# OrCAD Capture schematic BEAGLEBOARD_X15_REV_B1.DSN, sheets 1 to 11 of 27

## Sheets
1 P01_TITLE PAGE: title: BeagleBoard-X15; rev: B1; note: BeagleBoard-X15-_B.dsn
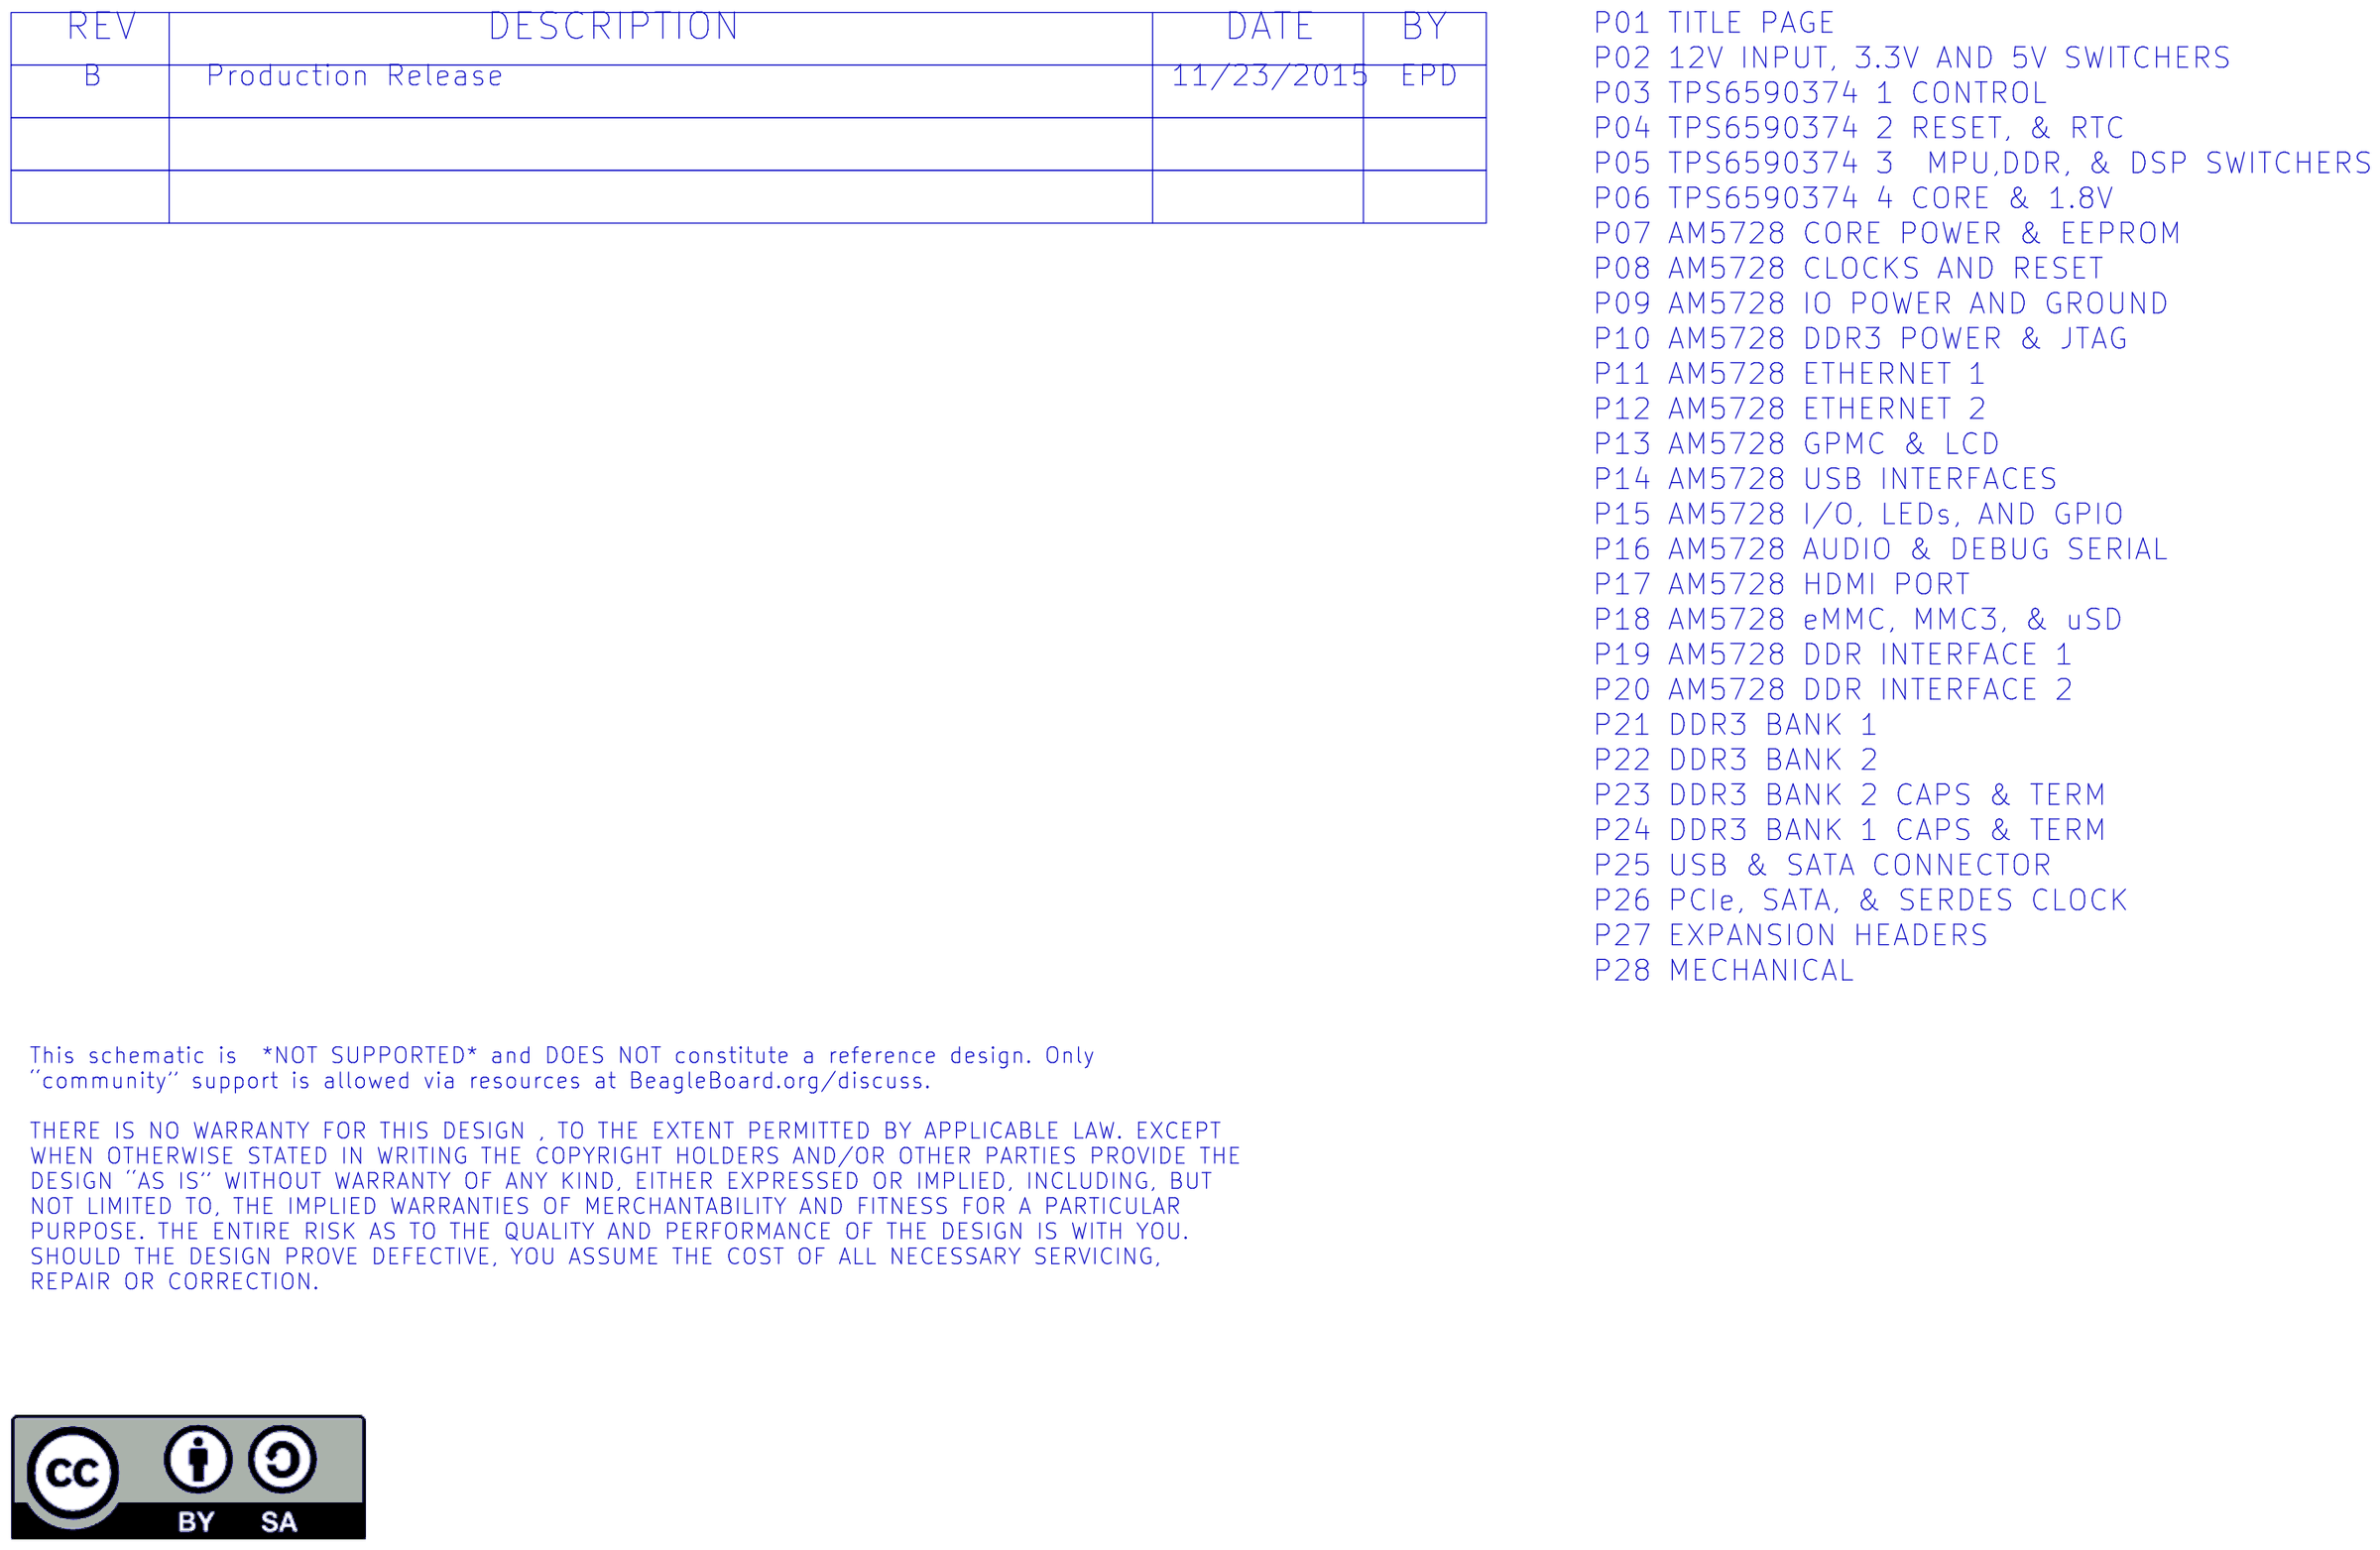
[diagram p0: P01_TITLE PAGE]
2 P02_12V IN, 3.3V & 5V SWITCHERS: size B; title: BeagleBoard-X15 12V in,3,3V & 5V SWITCHERS; note: BeagleBoard-X15_A2.dsn
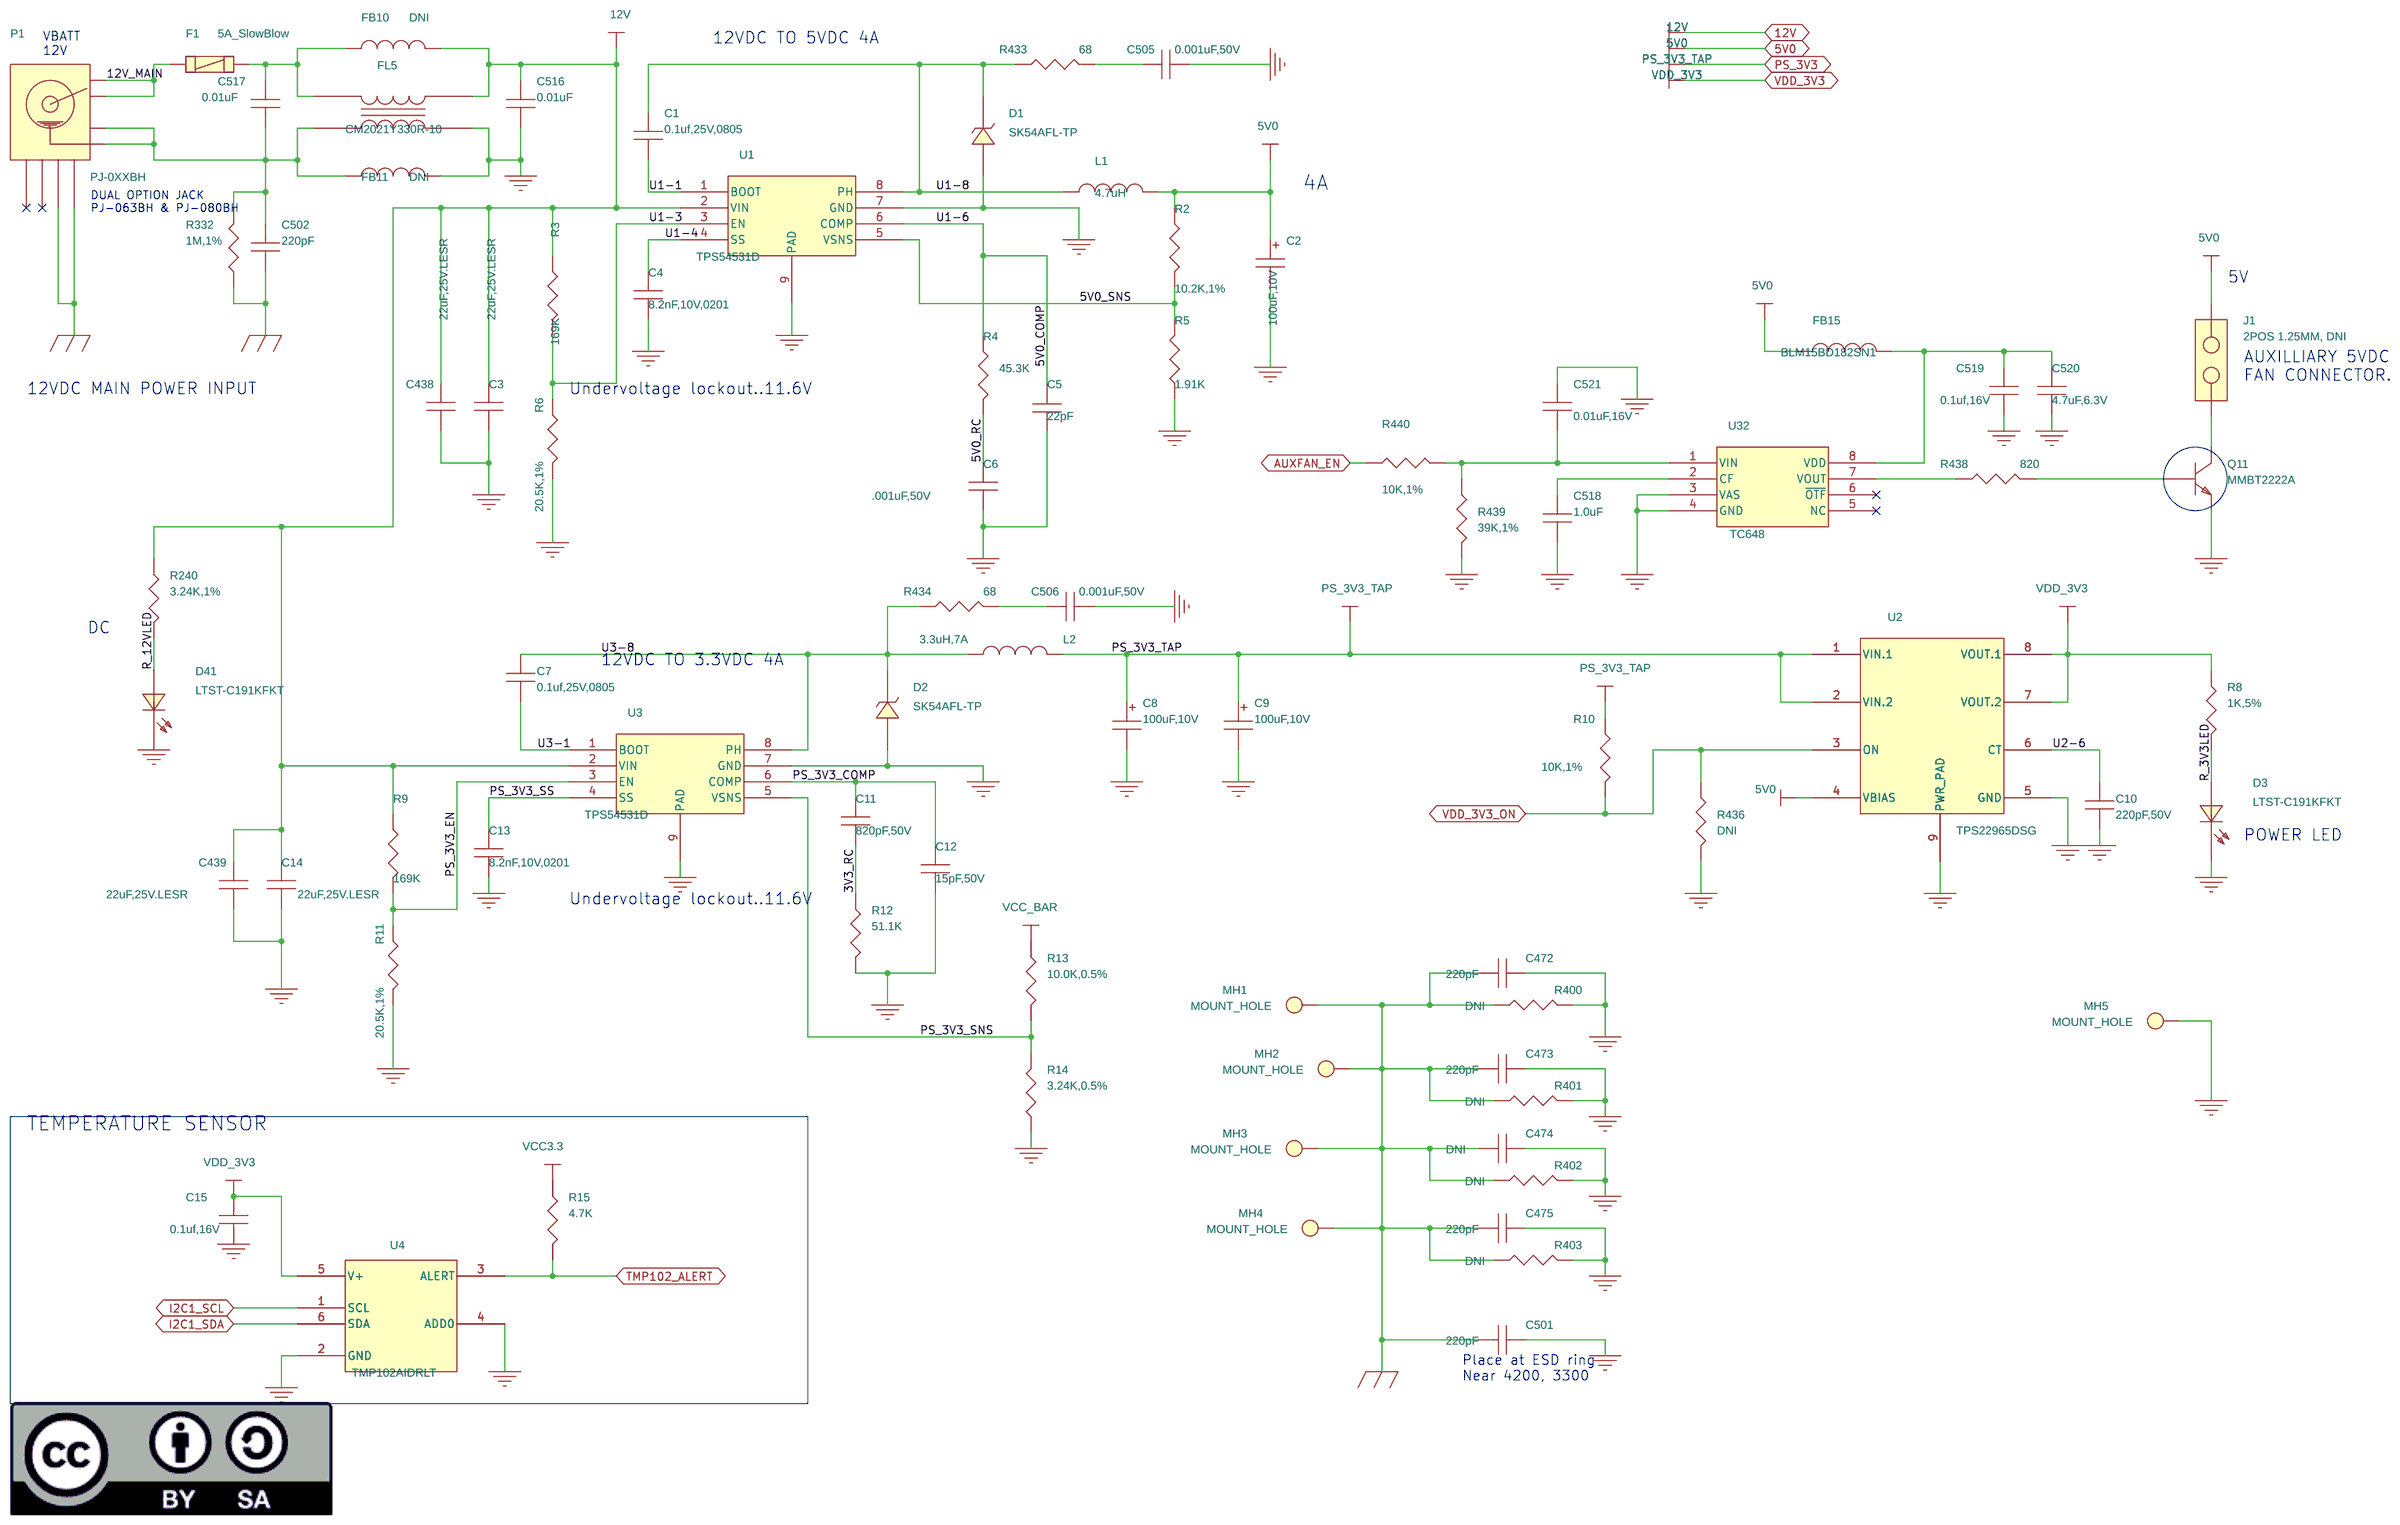
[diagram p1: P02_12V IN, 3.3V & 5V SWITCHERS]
3 P03_TPS6590376 CONTROL: size B; title: BeagleBoard-X15 TPS6590371 CONTROL; note: BeagleBoard-X15_B.dsn
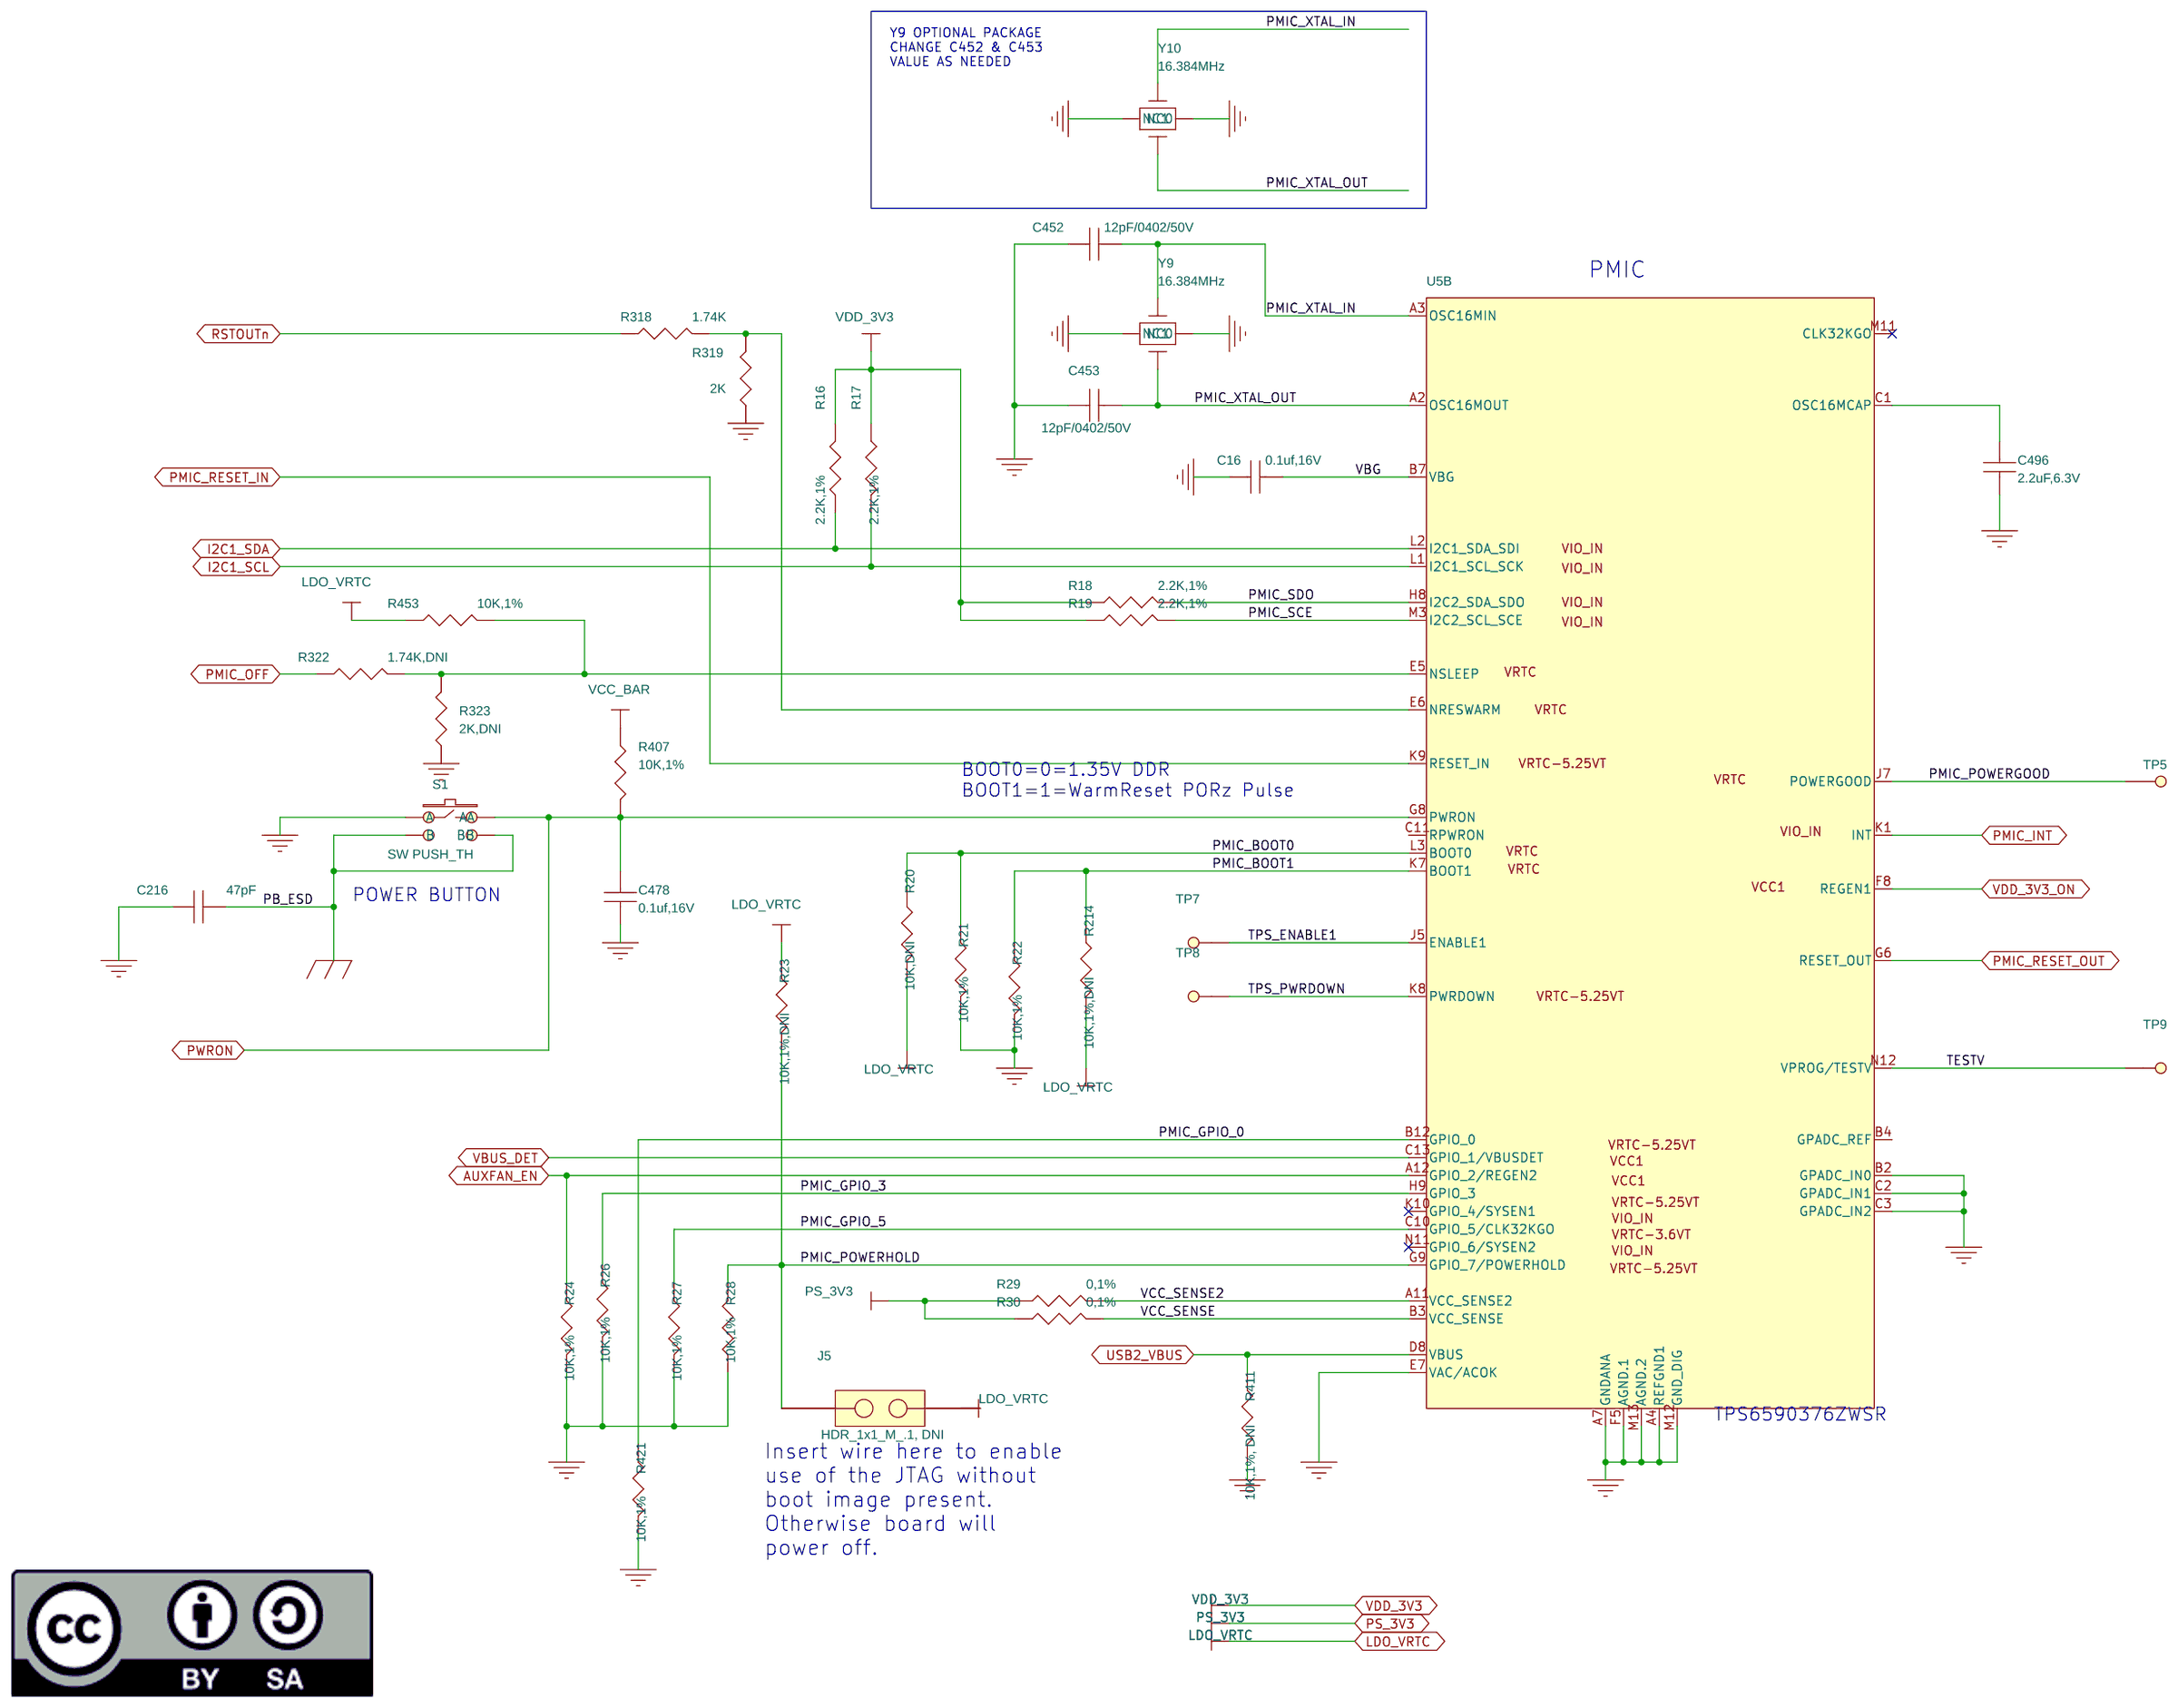
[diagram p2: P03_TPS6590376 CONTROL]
4 P04_TPS6590376 2, LDO & RTC: size B; title: BeagleBoard-X15 TPS6590371 CONTROL; note: BeagleBoard-X15_B.dsn
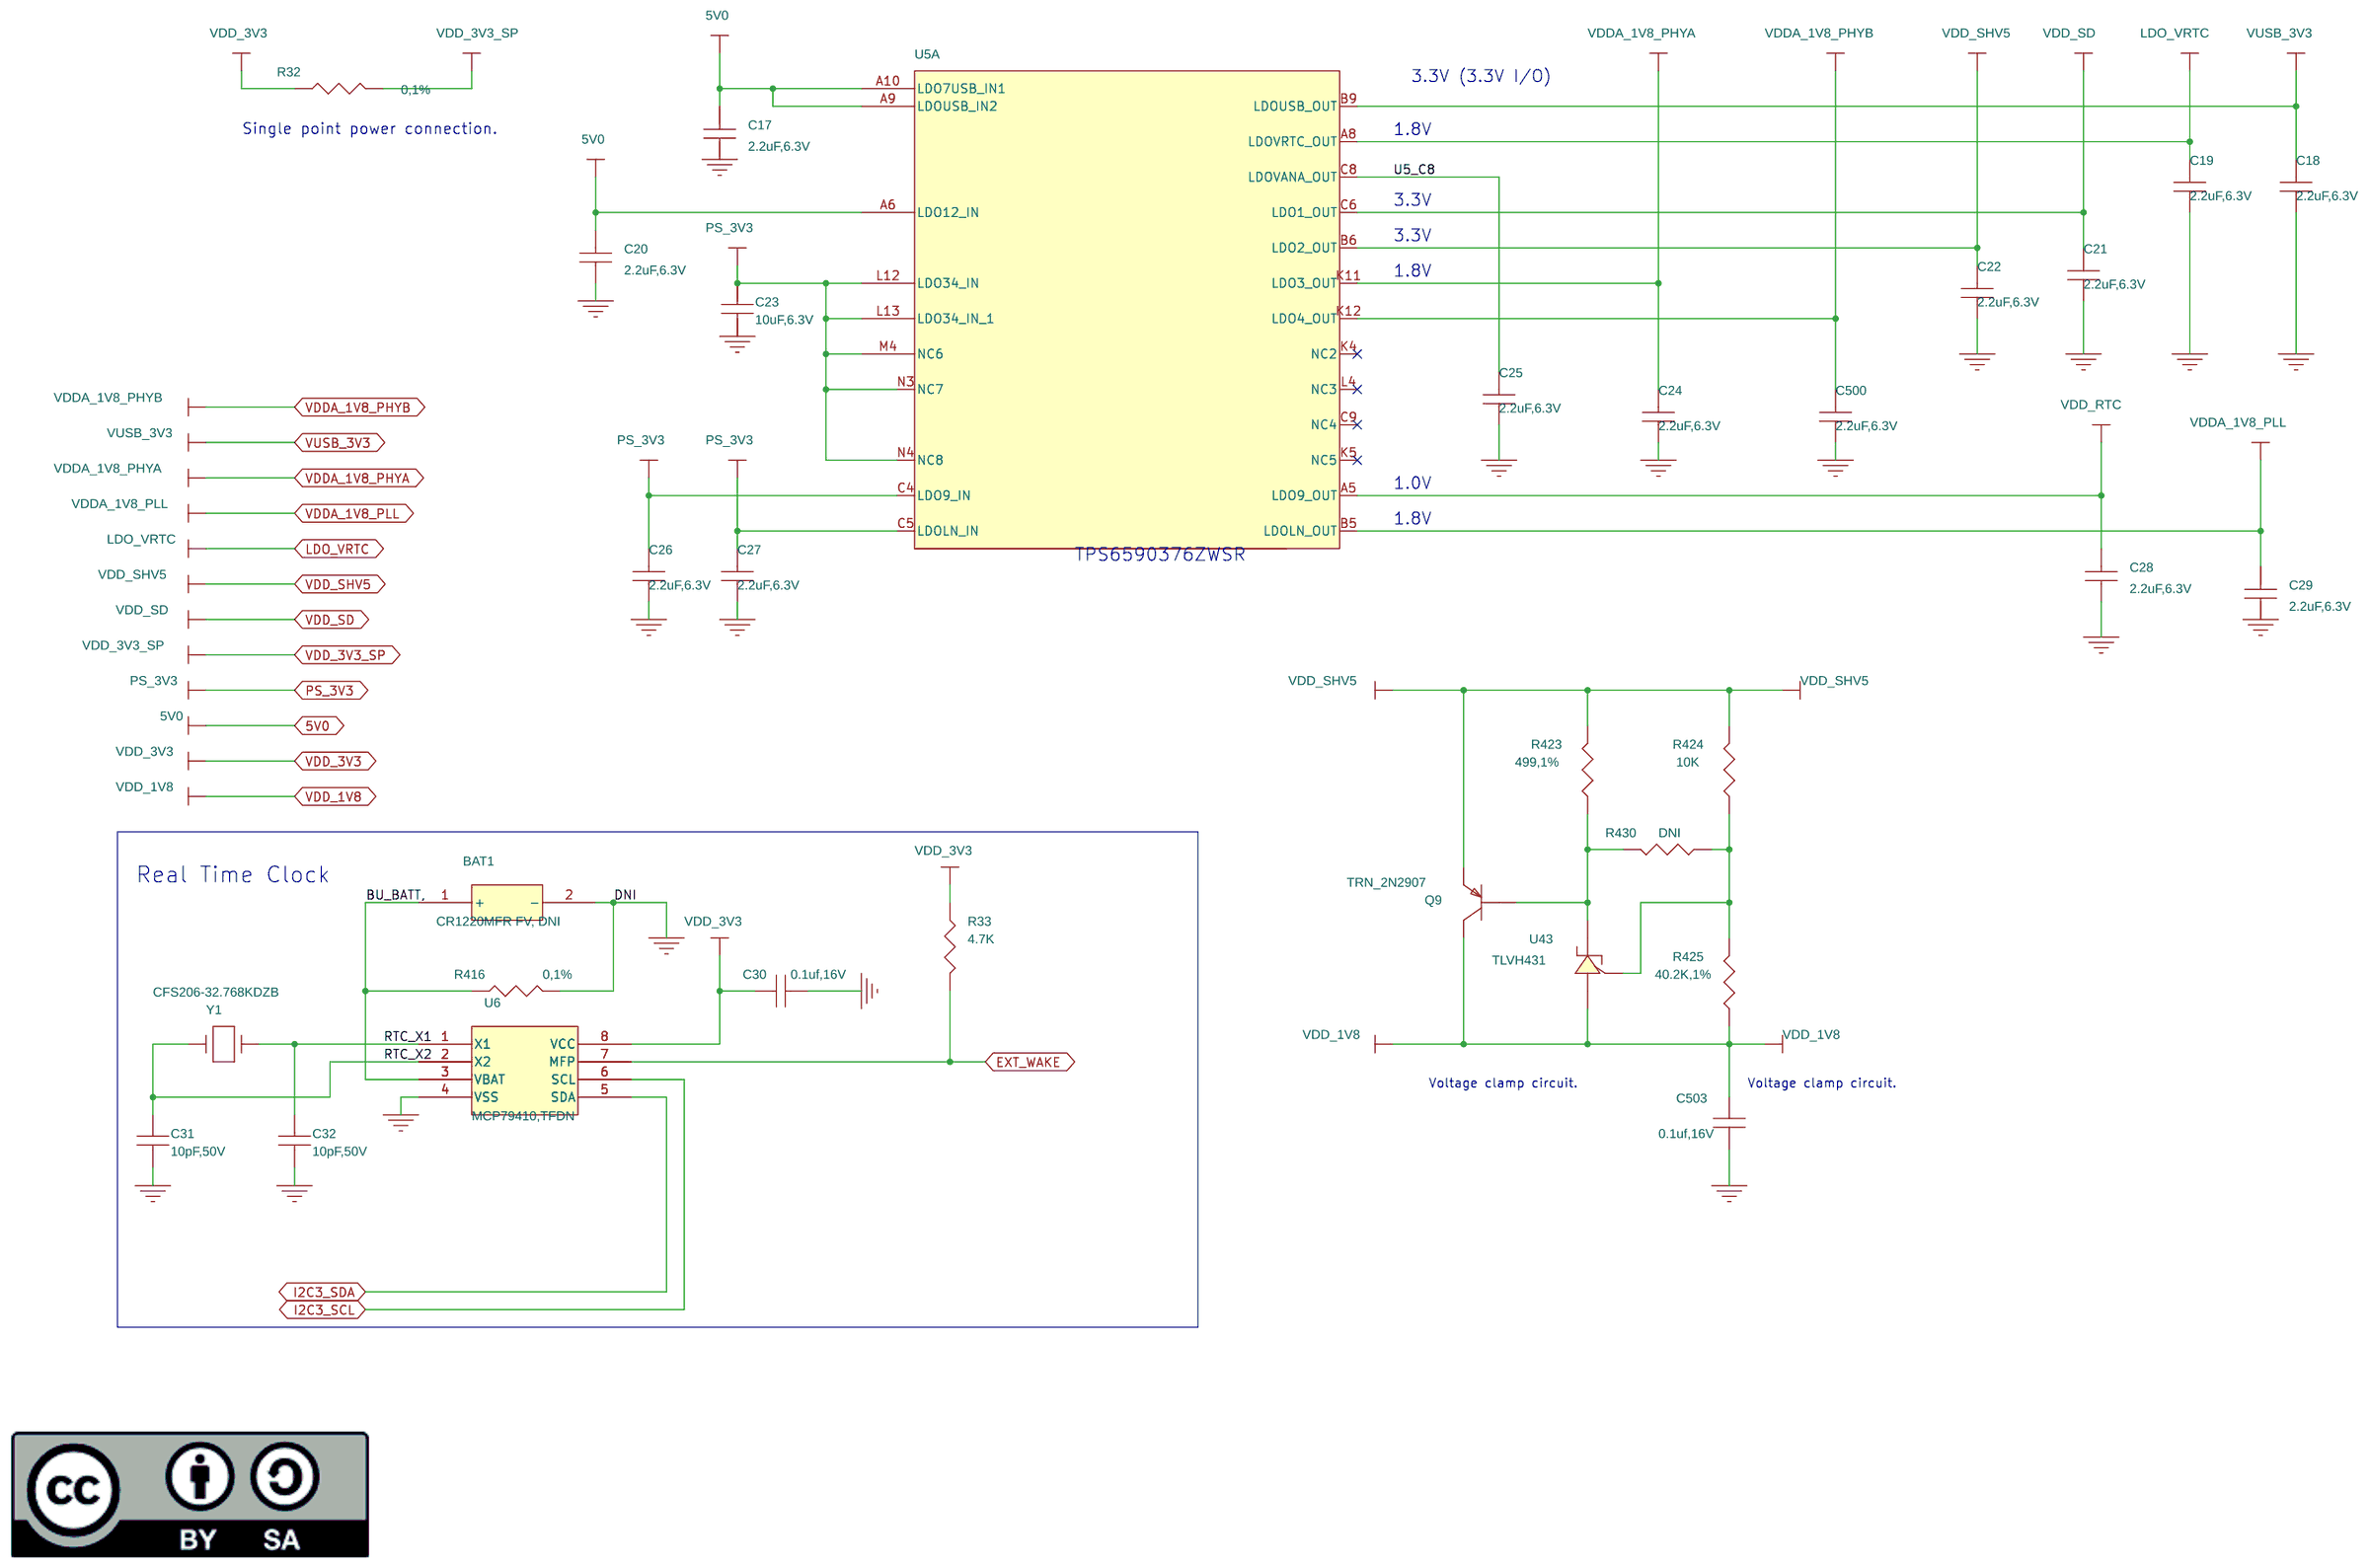
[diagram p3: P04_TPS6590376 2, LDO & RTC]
5 P05_TPS6590376 3 MPU,DSP SWITCH: size B; title: BeagleBoard-X15 TPS6590371 MPU, DDR, & DSP; note: BeagleBoard-X15_B.dsn
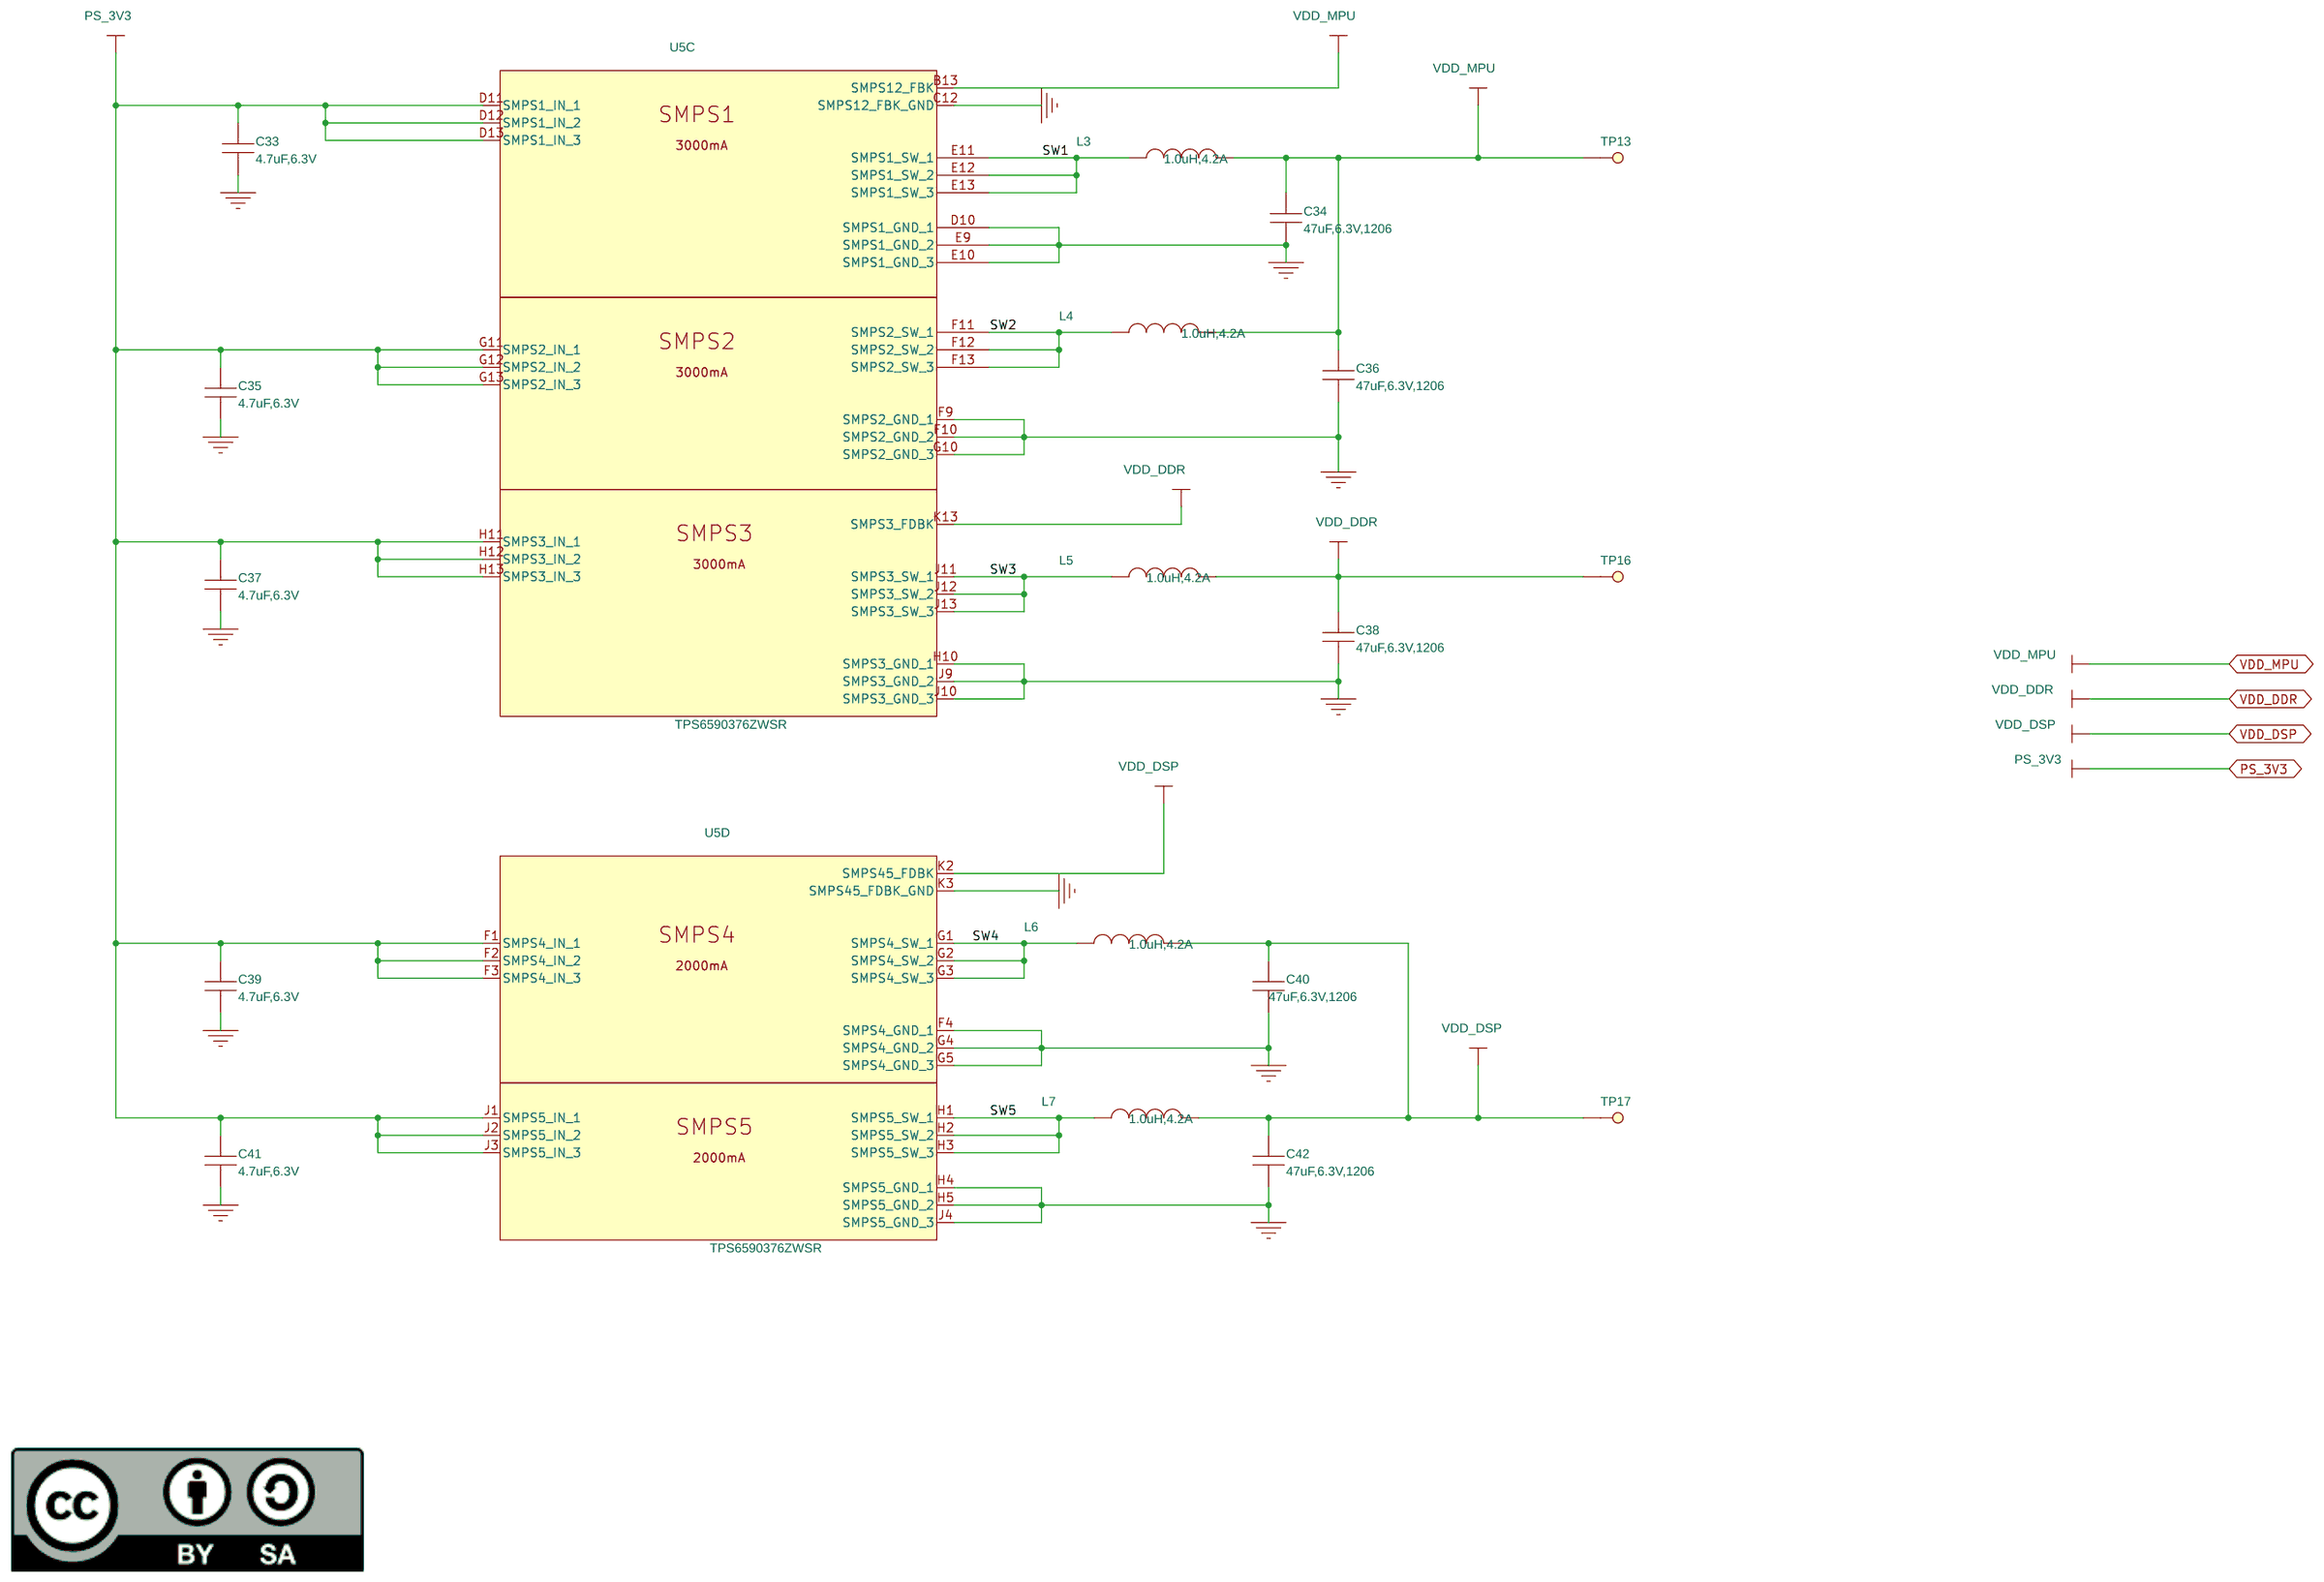
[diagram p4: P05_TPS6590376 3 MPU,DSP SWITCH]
6 P06_TPS6590376 4 CORE & 1.8V: size B; title: BeagleBoard-X15 TPS6590374 SWITCHERS; note: BeagleBoard-X15_B.dsn
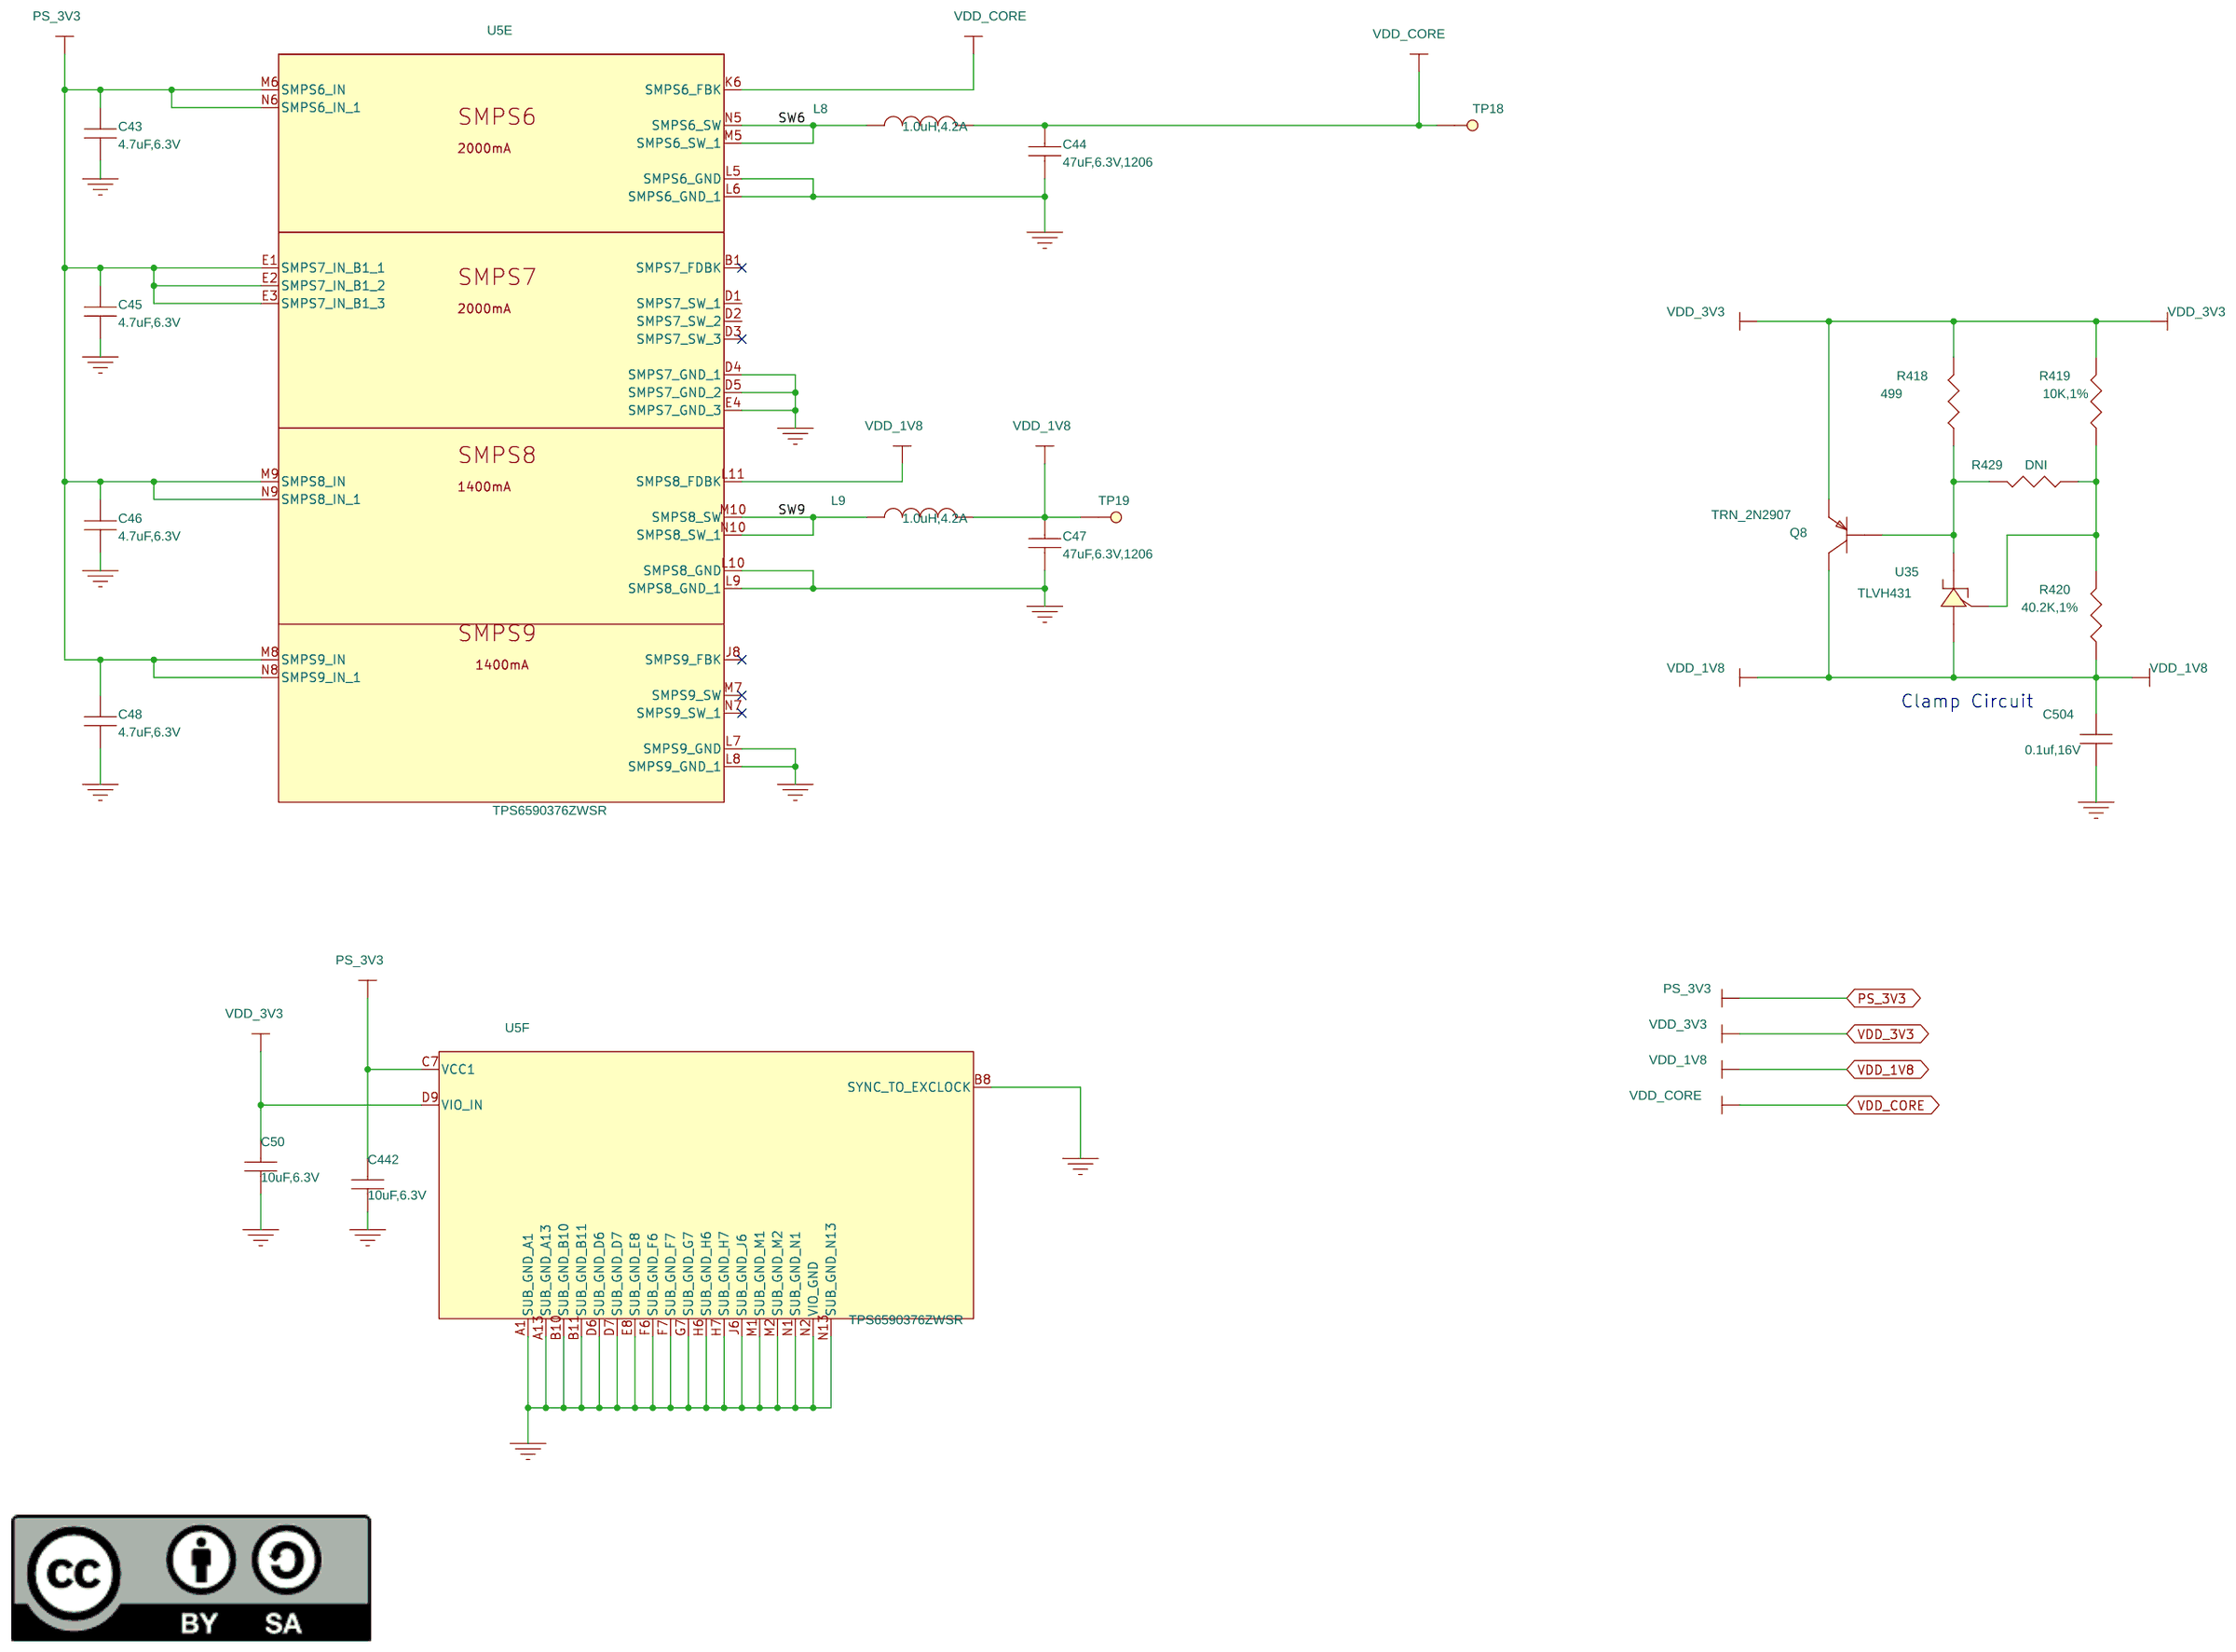
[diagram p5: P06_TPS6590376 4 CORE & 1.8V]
7 P07_AM572x CORE POWER & EEPROM: size B; title: BeagleBoard-X15 AM5728 CORE POWER; note: BeagleBoard-X15_B.dsn
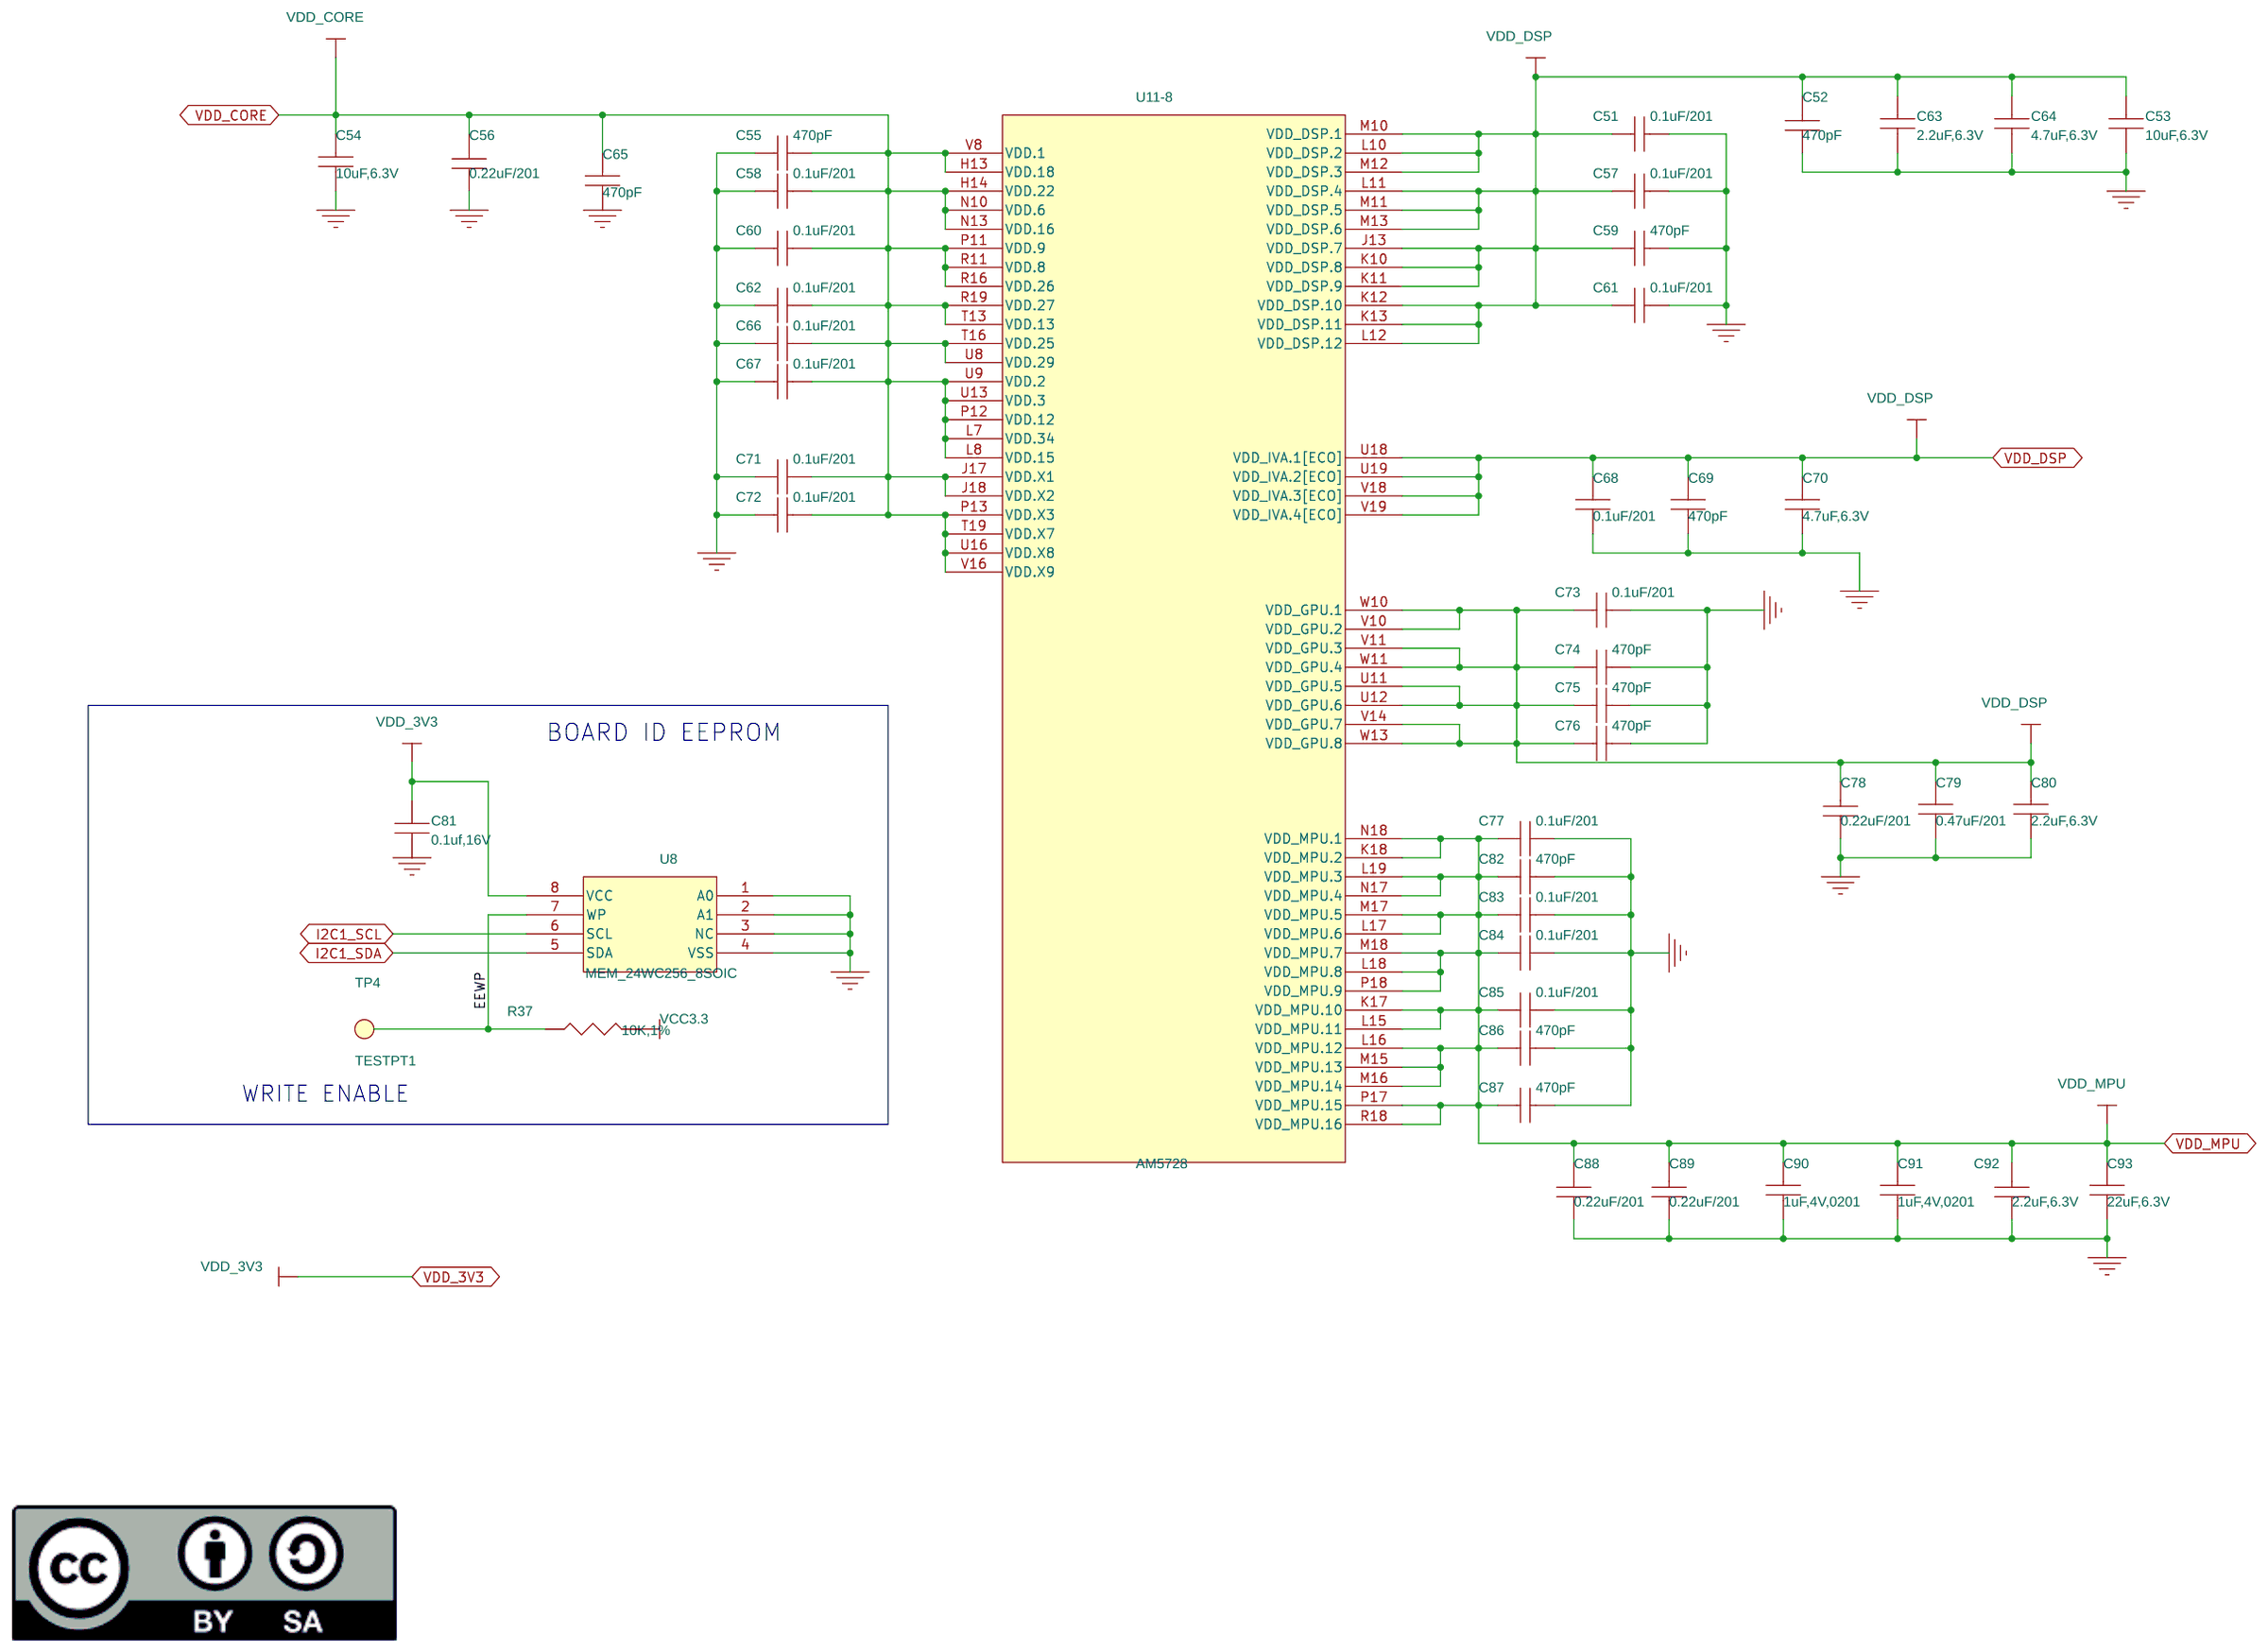
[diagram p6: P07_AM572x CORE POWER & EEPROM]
8 P08_AM572x CLOCKS & RESET: size B; title: BeagleBoard-X15 AM572X CLOCKS & RESET; note: BeagleBoard-X15_B.dsn
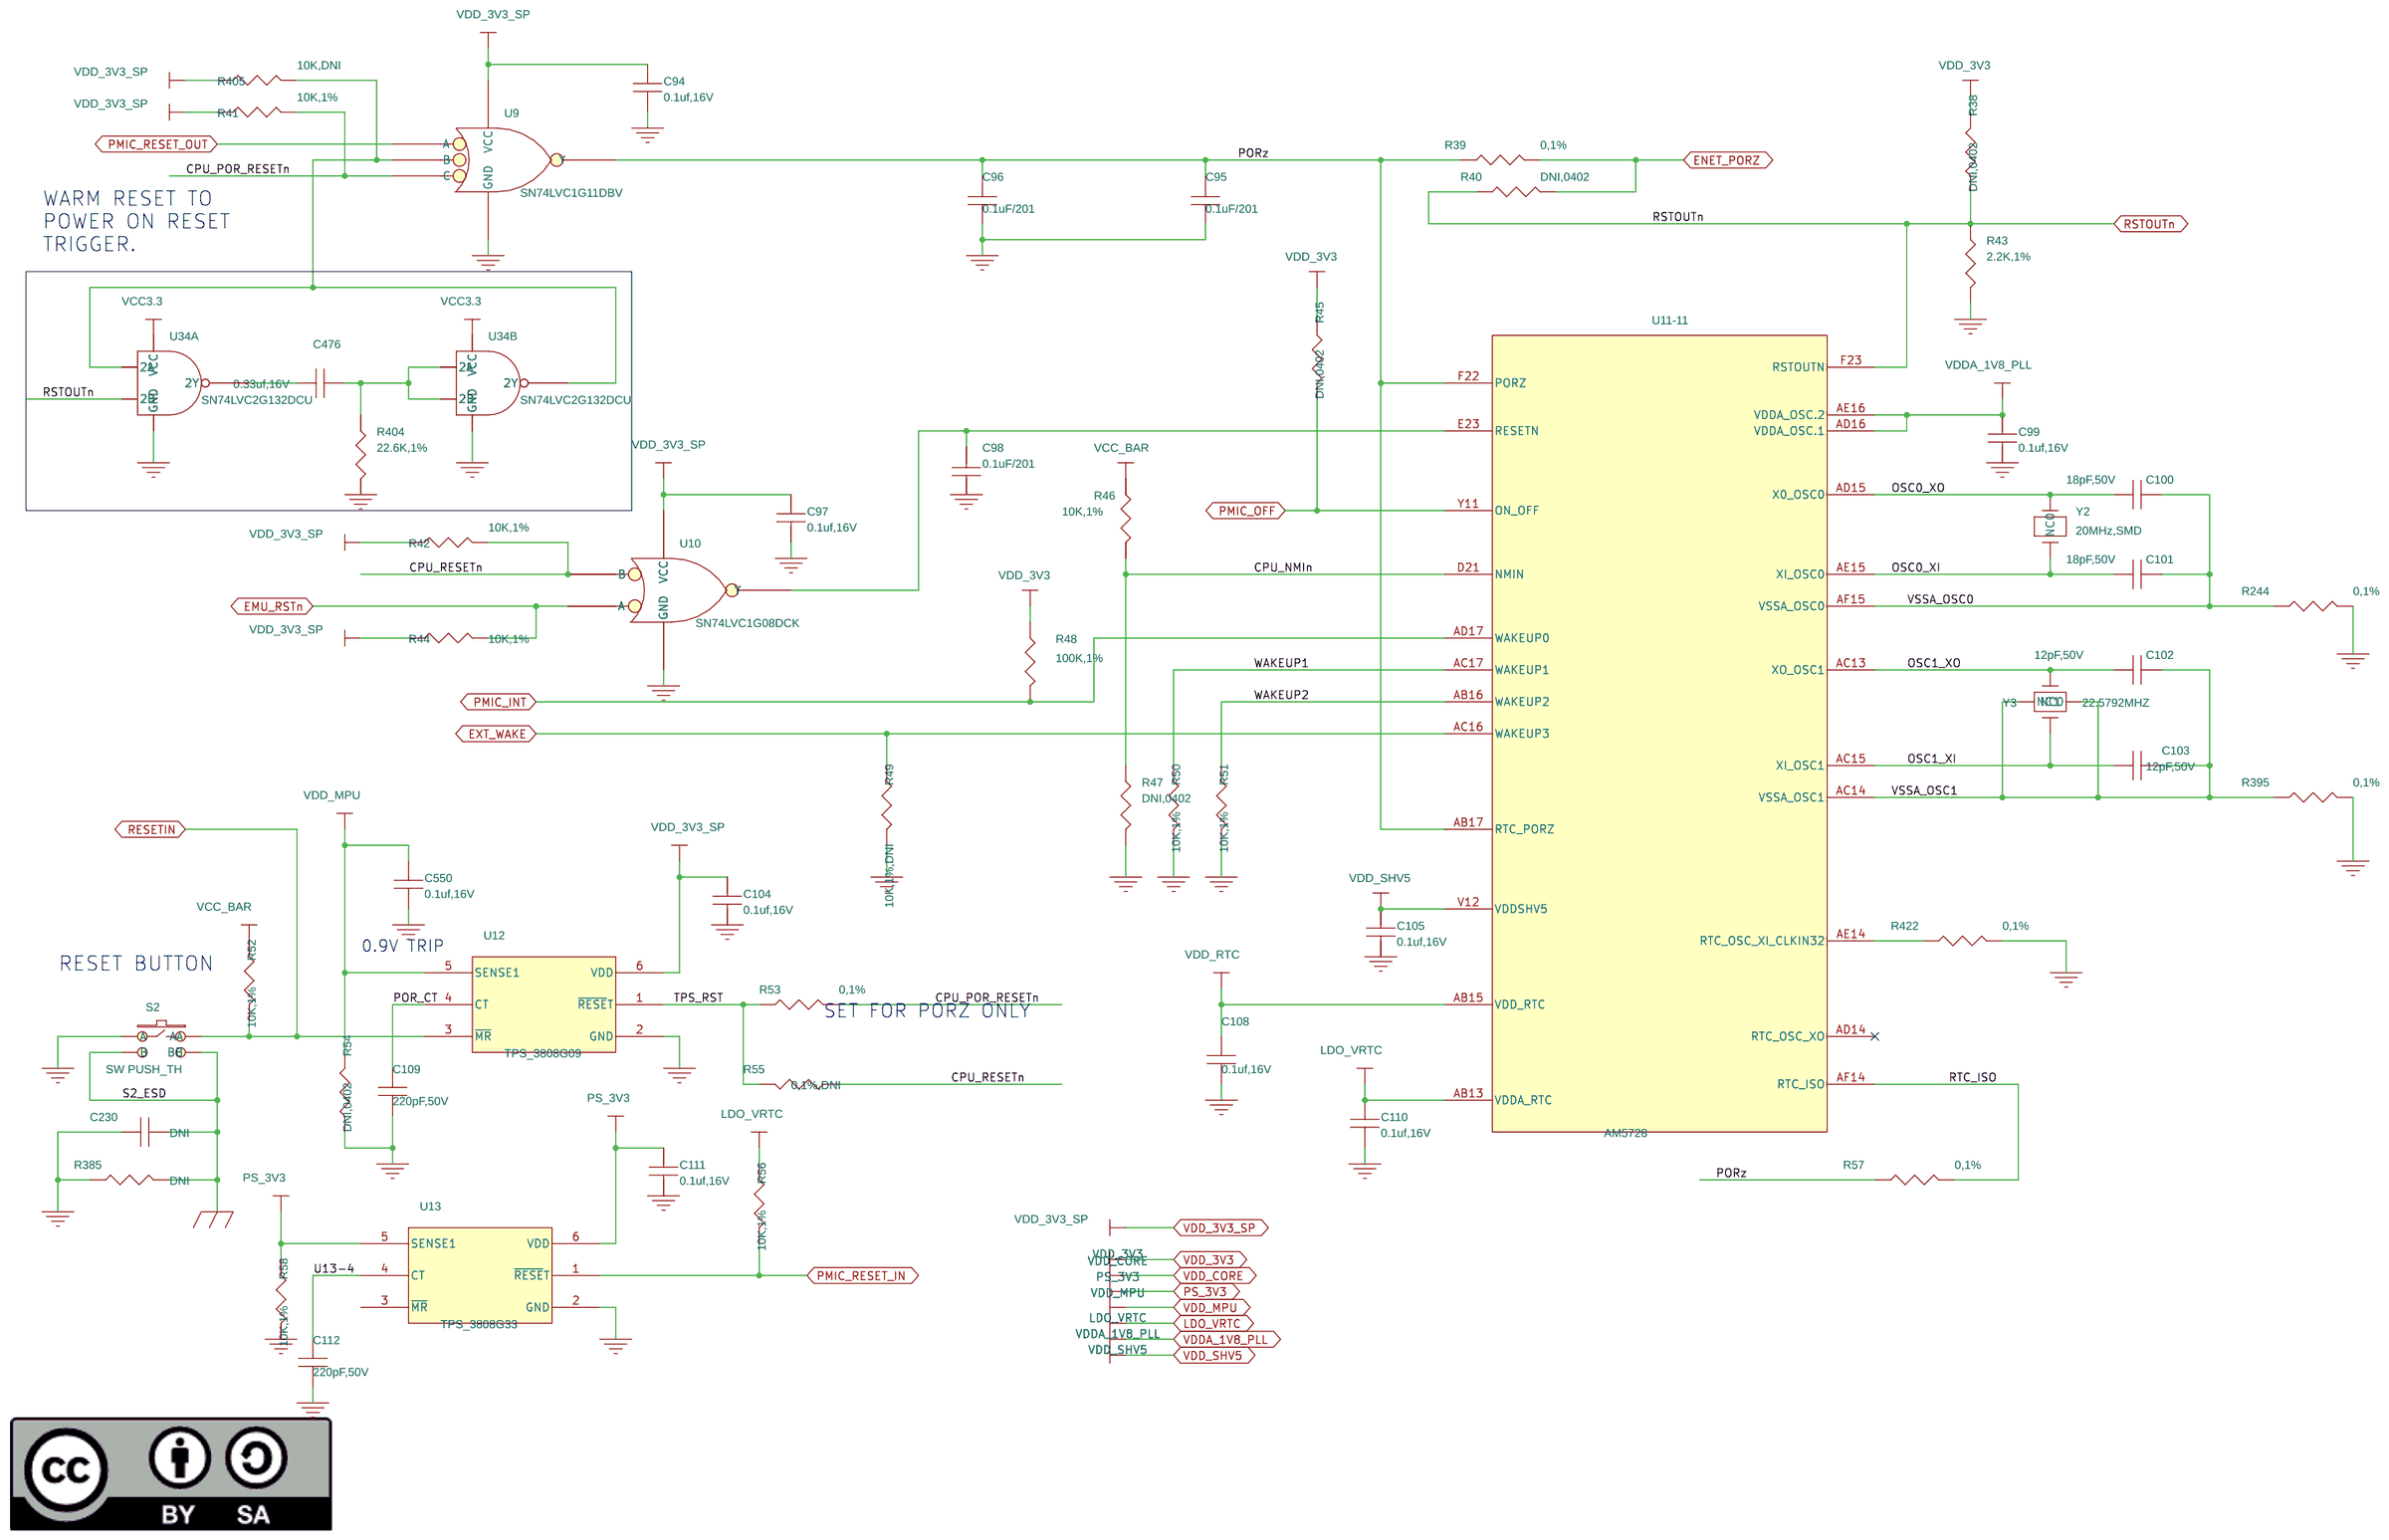
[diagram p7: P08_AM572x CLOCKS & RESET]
9 P09 AM572x_IO POWER & GND: size B; title: BeagleBoard-X15 AM572X I/O POWER & GROUND; note: BeagleBoard-X15_B.dsn
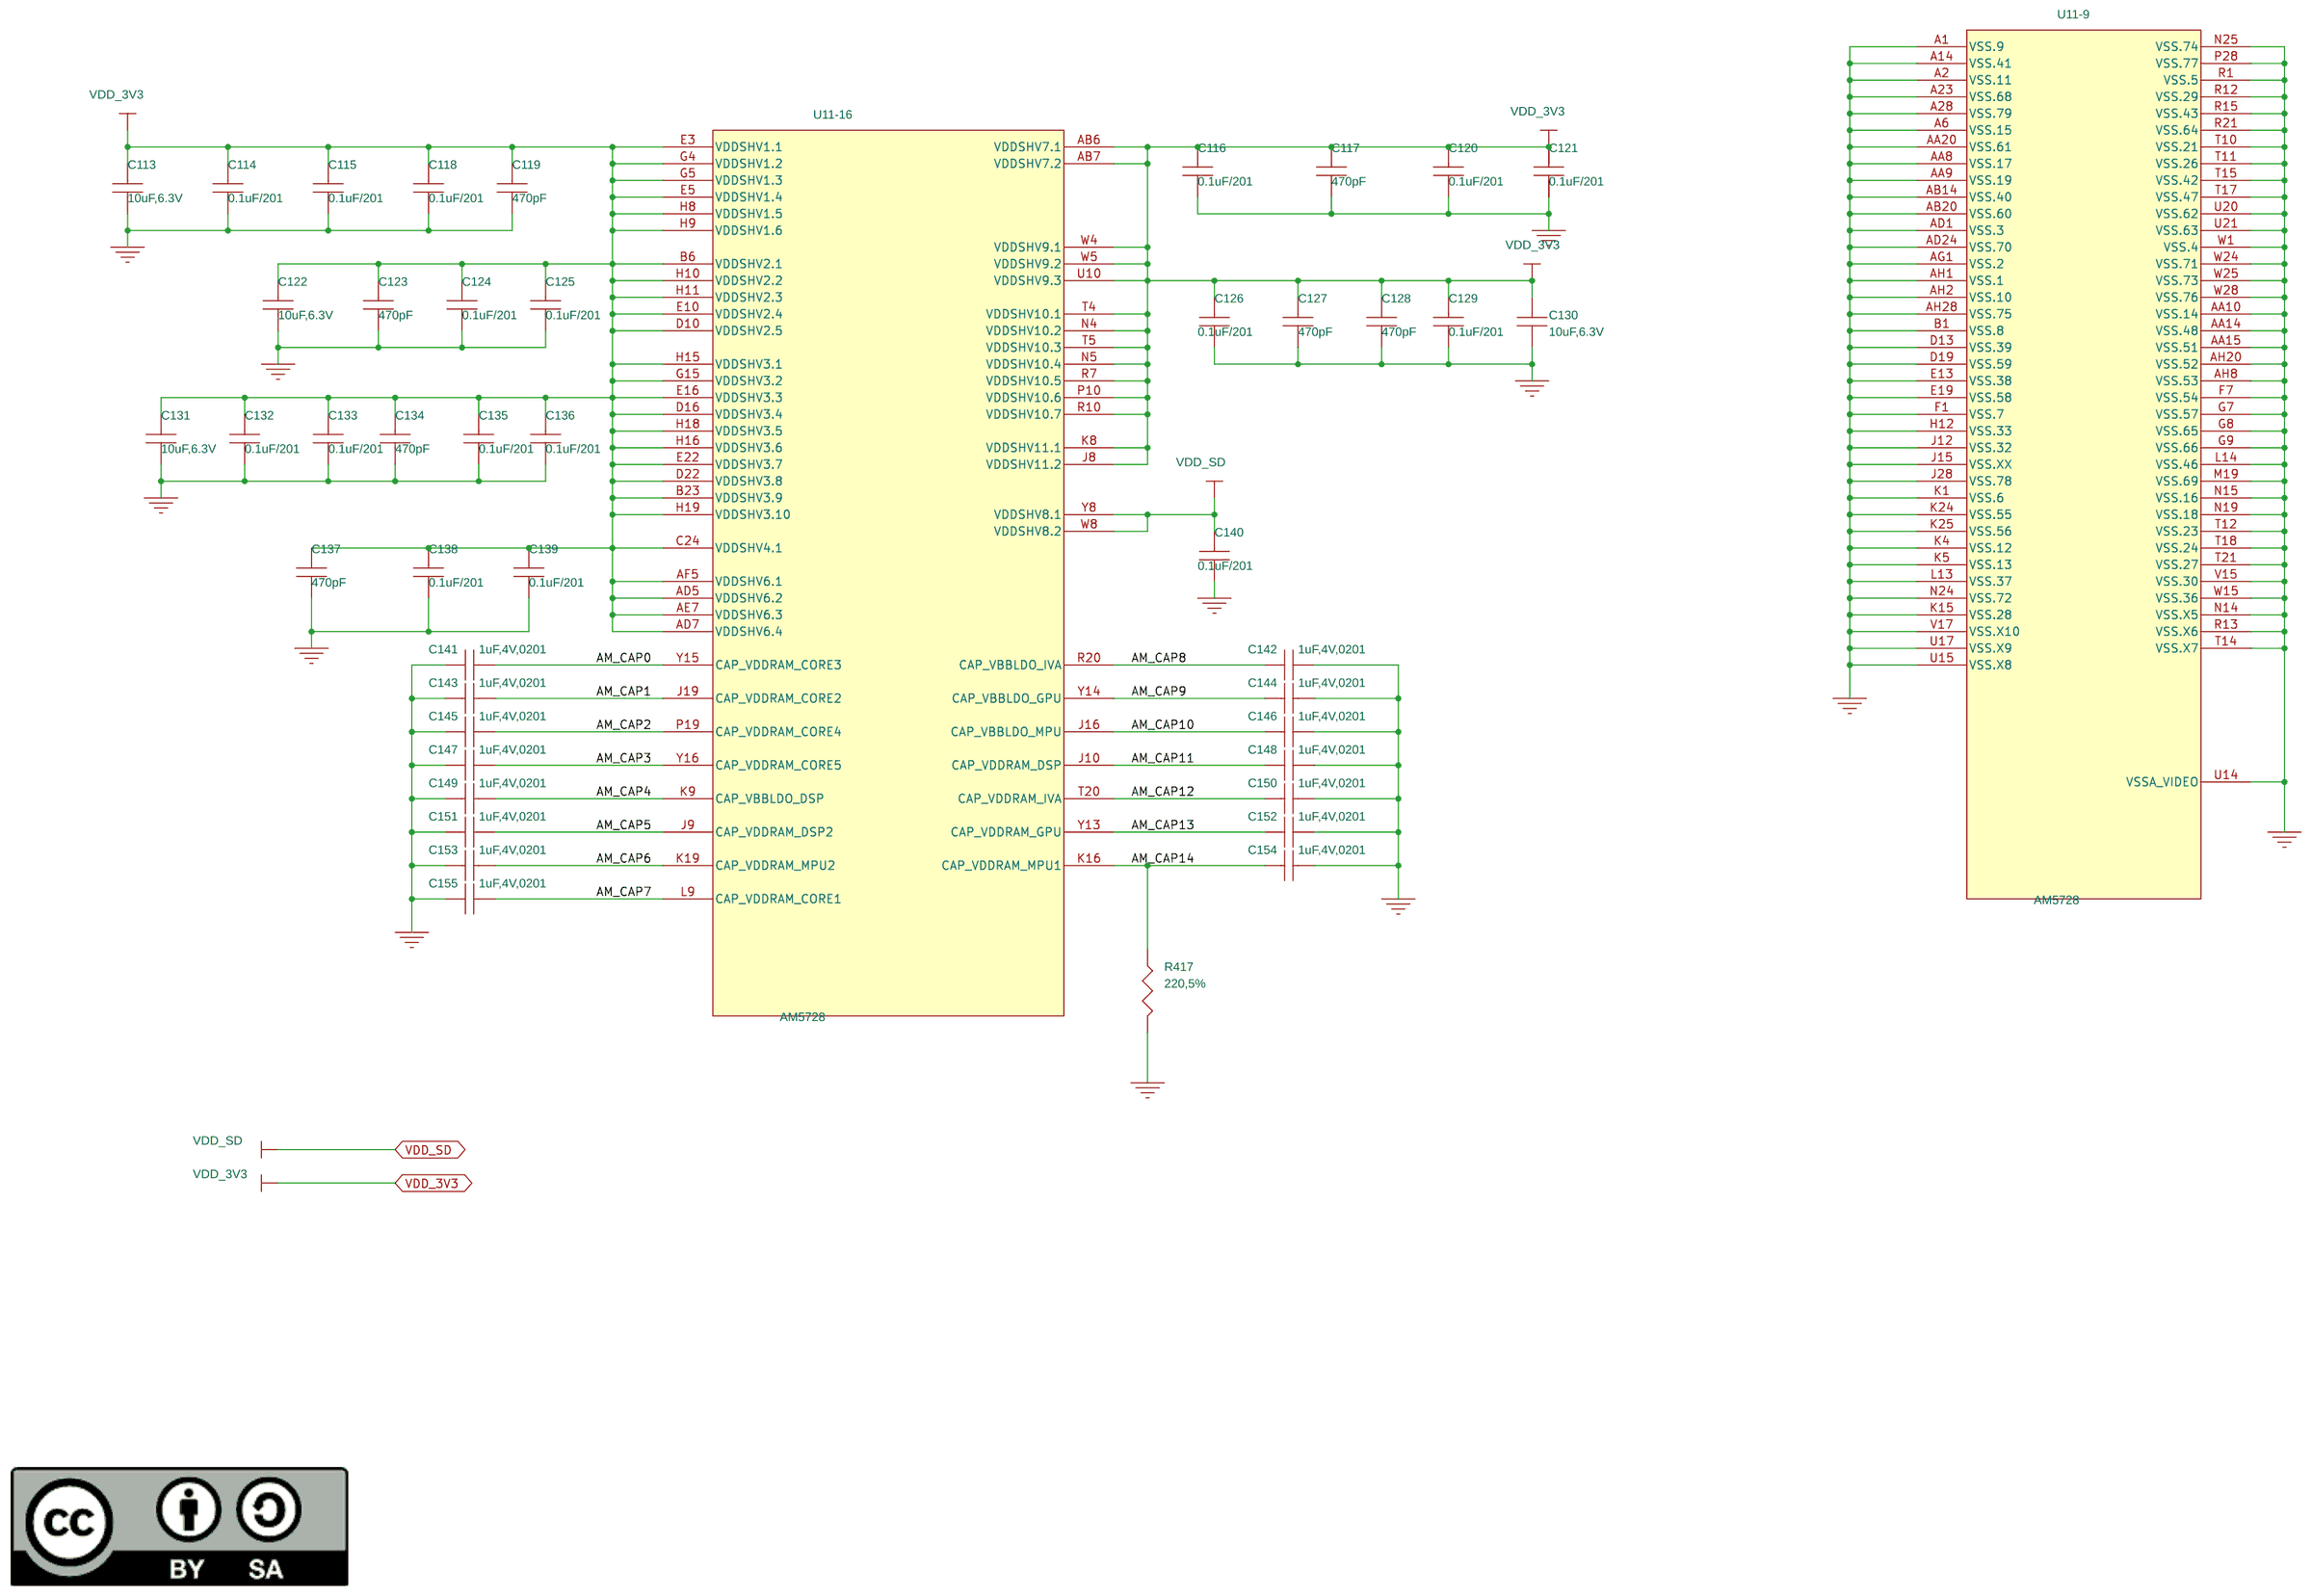
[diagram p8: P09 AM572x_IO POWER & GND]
10 P10_AM572x  DDR3 POWER, & JTAG: size B; title: BeagleBoard-X15 AM572X 1.8V & DDR POWER; note: BeagleBoard-X15_B.dsn
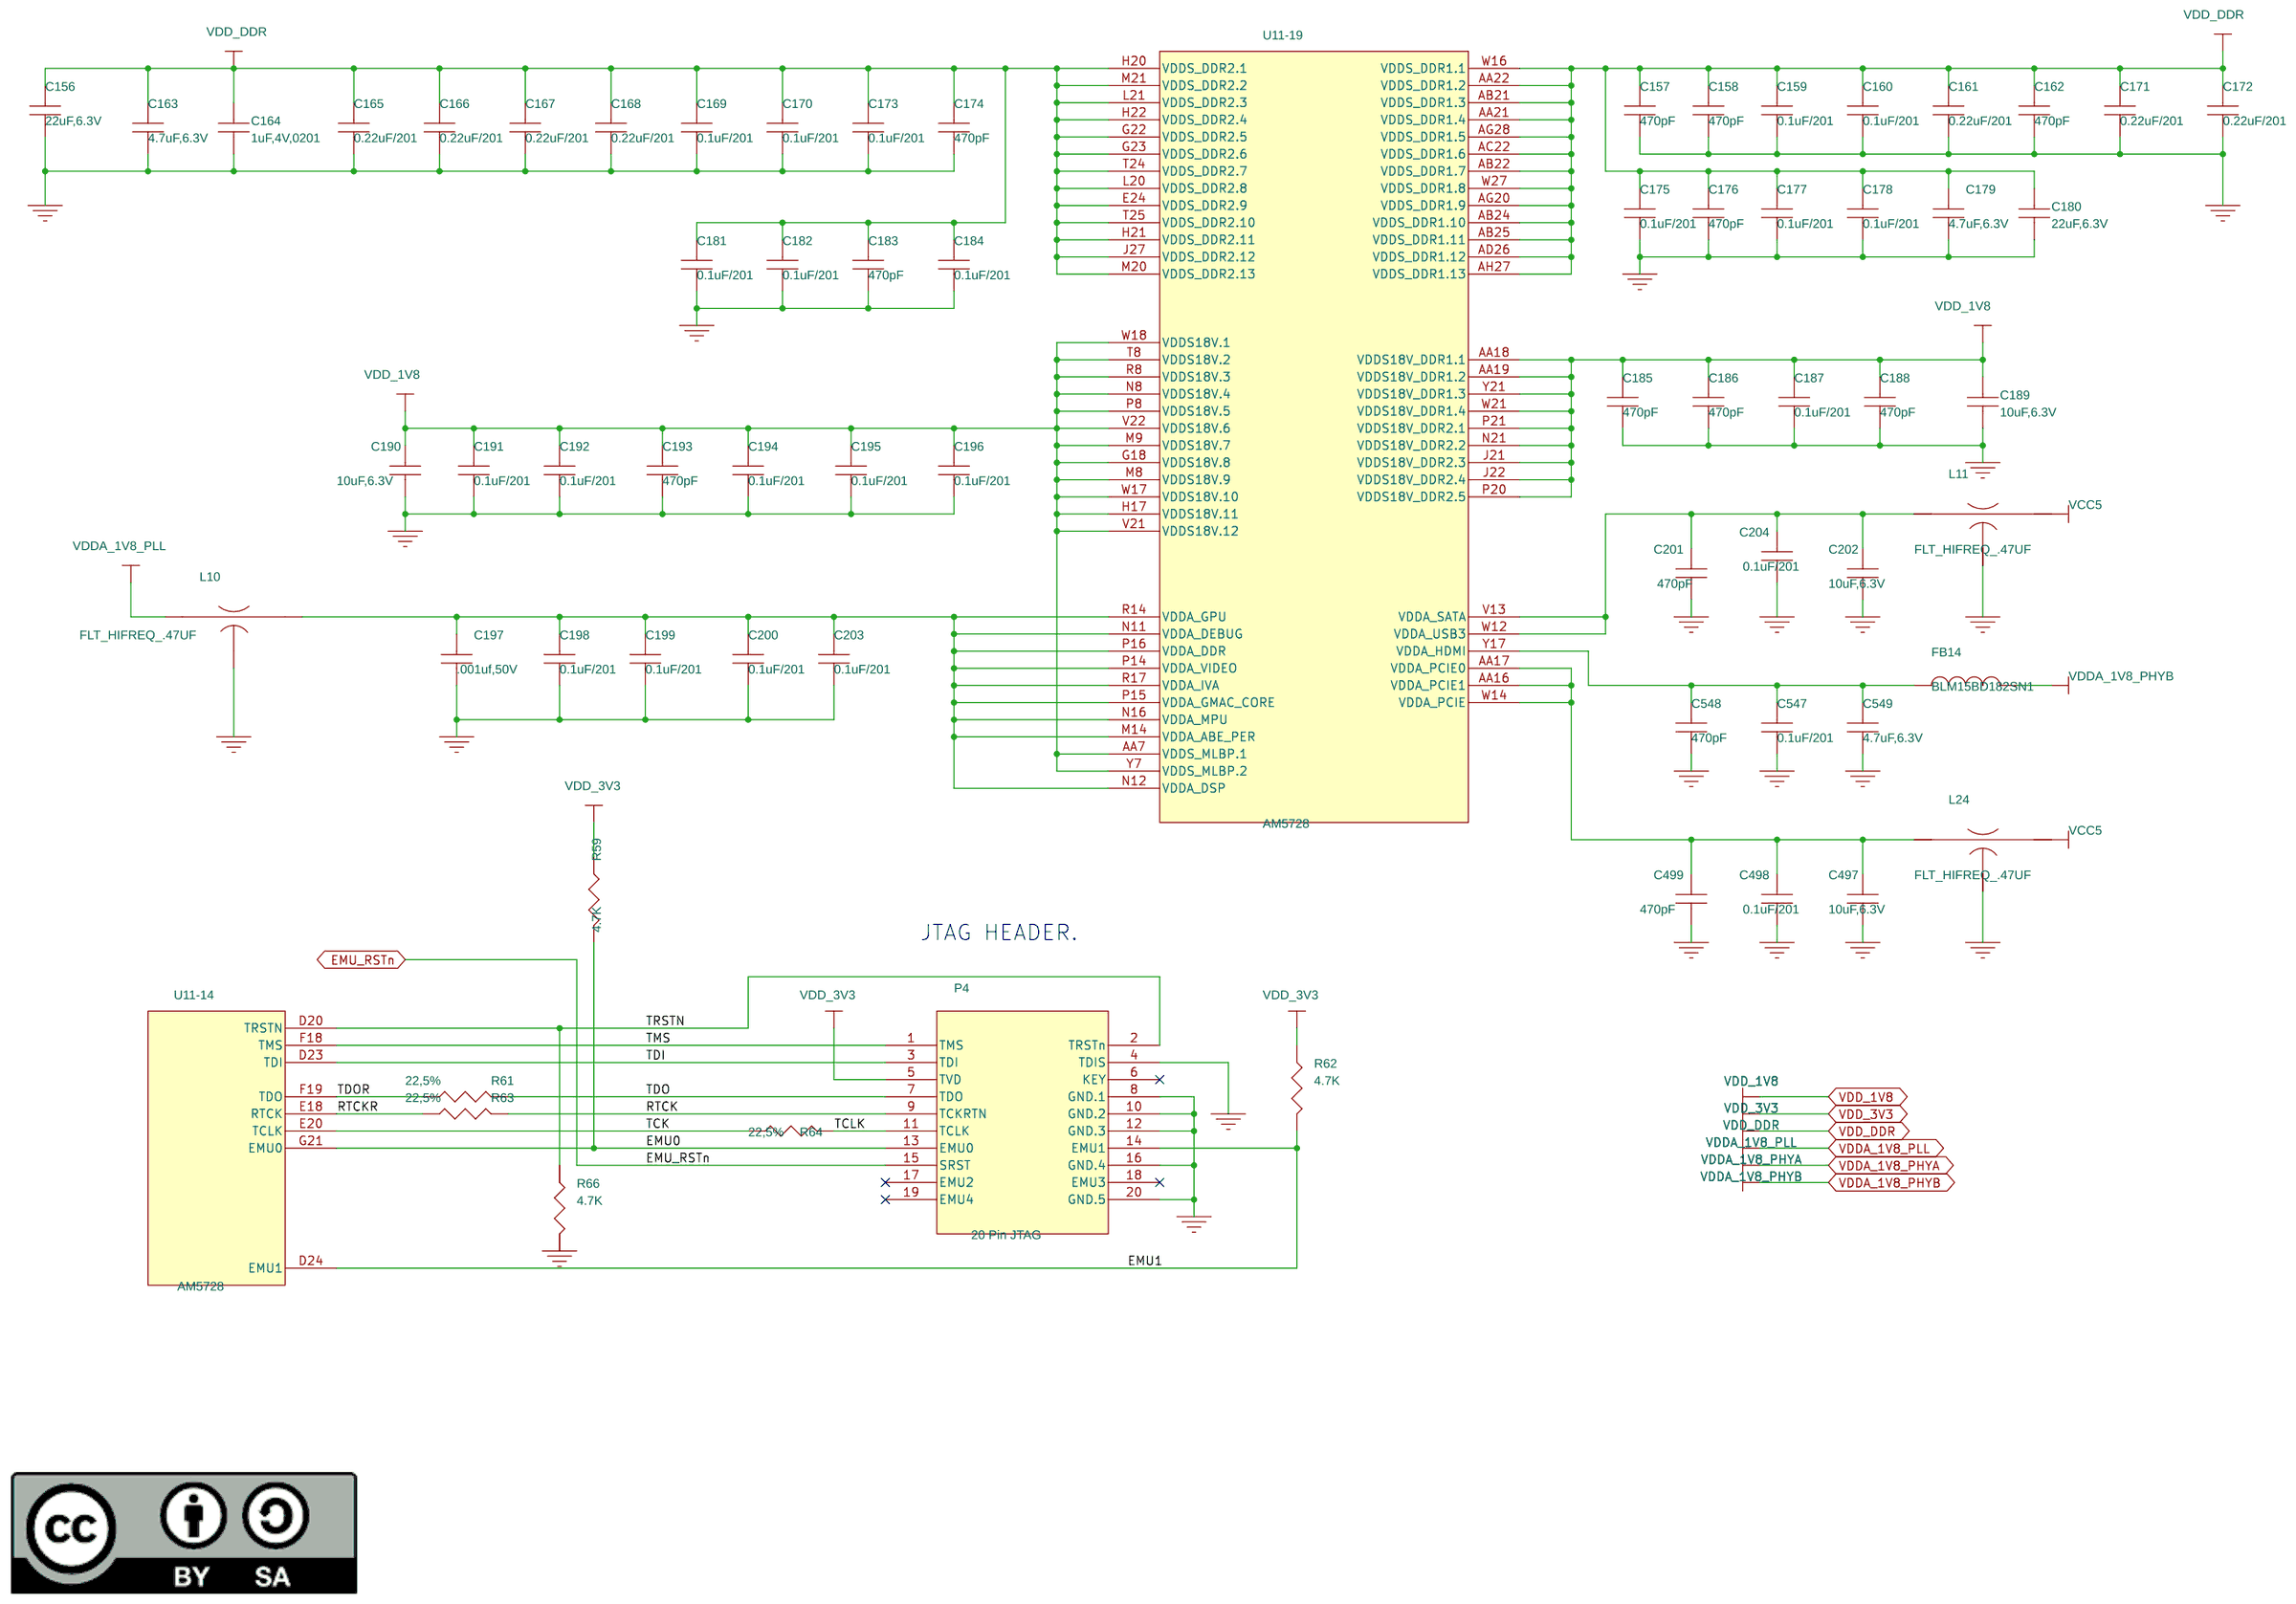
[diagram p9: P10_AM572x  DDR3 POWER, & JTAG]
11 P11_AM572x ETHERNET 0: size B; title: BeagleBoard-X15 ETHERNET PORT 0; note: BeagleBoard-X15_B.dsn
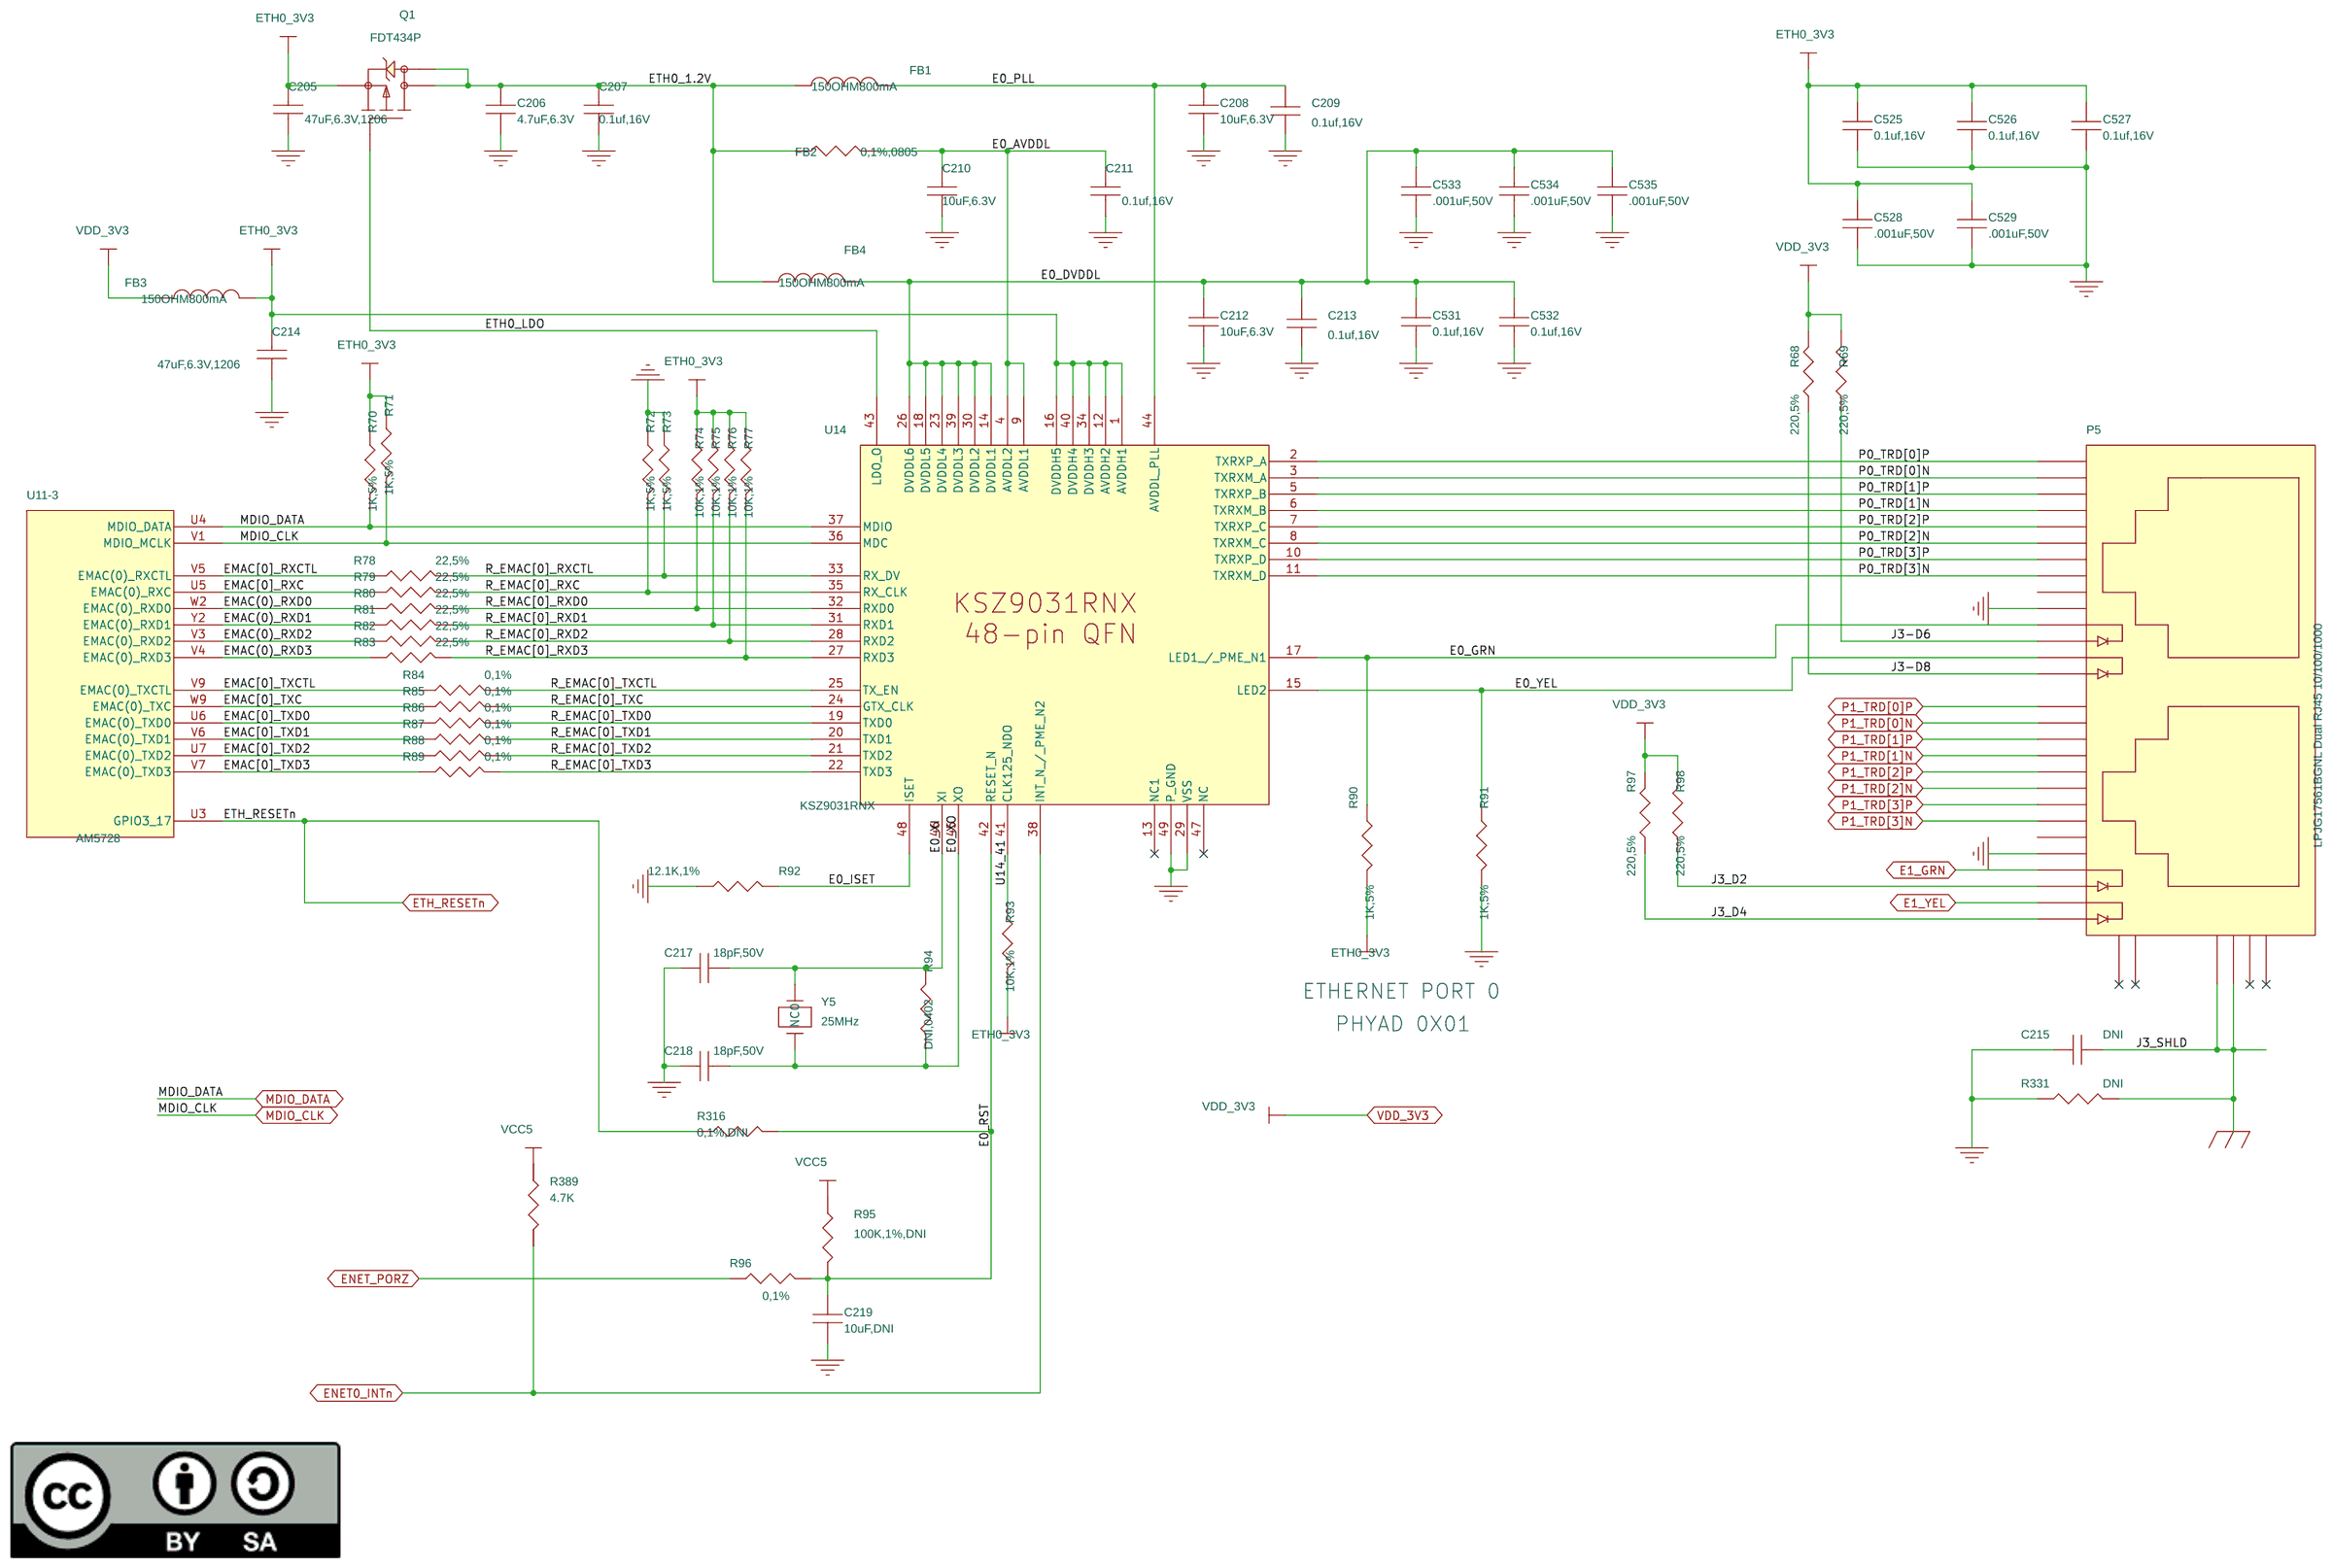
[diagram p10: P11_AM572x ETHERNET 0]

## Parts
sheet P02_12V IN, 3.3V & 5V SWITCHERS
C1  0.1uf,25V,0805  [805]
C2  100uF,10V  [6032]
C3  22uF,25V.LESR  [1210]
C4  8.2nF,10V,0201  [201]
C5  22pF  [402]
C6  .001uF,50V  [402]
C7  0.1uf,25V,0805  [805]
C8  100uF,10V  [6032]
C9  100uF,10V  [6032]
C10  220pF,50V  [805]
C11  820pF,50V  [805]
C12  15pF,50V  [805]
C13  8.2nF,10V,0201  [201]
C14  22uF,25V.LESR  [1210]
C15  0.1uf,16V  [402]
C438  22uF,25V.LESR  [1210]
C439  22uF,25V.LESR  [1210]
C472  220pF  [402]
C473  220pF  [402]
C474  DNI  [402]
C475  220pF  [402]
C501  220pF  [402]
C502  220pF  [402]
C505  0.001uF,50V  [603]
C506  0.001uF,50V  [603]
C516  0.01uF  [402]
C517  0.01uF  [402]
C518  1.0uF  [402]
C519  0.1uf,16V  [402]
C520  4.7uF,6.3V  [402]
C521  0.01uF,16V  [402]
D1  SK54AFL-TP  [DO221AC]
D2  SK54AFL-TP  [DO221AC]
D3  LTST-C191KFKT  [LED_603]
D41  LTST-C191KFKT  [LED_603]
F1  5A_SlowBlow  [FU250_200X400SMD]
FB10  DNI  [1206]
FB11  DNI  [1206]
FB15  BLM15BD182SN1  [402]
FL5  CM2021Y330R-10  [cmc_cm2021y]
J1  2POS 1.25MM, DNI  [CON2_49LS]
L1  4.7uH  [IND130_208X216]
L2  3.3uH,7A  [IND130_208X216]
MH1  MOUNT_HOLE  [MTGH250C125D_PL]
MH2  MOUNT_HOLE  [MTGH250C125D_PL]
MH3  MOUNT_HOLE  [MTGH250C125D_PL]
MH4  MOUNT_HOLE  [MTGH250C125D_PL]
MH5  MOUNT_HOLE  [MTGH200c102D_PL]
P1  PJ-0XXBH  [jack_pj-063-080bh]
Q11  MMBT2222A  [SOT-23]
R2  10.2K,1%  [402]
R3  169K  [402]
R4  45.3K  [402]
R5  1.91K  [402]
R6  20.5K,1%  [402]
R8  1K,5%  [402]
R9  169K  [402]
R10  10K,1%  [402]
R11  20.5K,1%  [402]
R12  51.1K  [402]
R13  10.0K,0.5%  [402]
R14  3.24K,0.5%  [402]
R15  4.7K  [402]
R240  3.24K,1%  [402]
R332  1M,1%  [402]
R400  DNI  [402]
R401  DNI  [402]
R402  DNI  [402]
R403  DNI  [402]
R433  68  [805]
R434  68  [805]
R436  DNI  [402]
R438  820  [402]
R439  39K,1%  [402]
R440  10K,1%  [402]
U1  TPS54531D  [DDA-8]
U2  TPS22965DSG  [WSON-8]
U3  TPS54531D  [DDA-8]
U4  TMP102AIDRLT  [SOT563]
U32  TC648  [SO8-25X75]
sheet P03_TPS6590376 CONTROL
C16  0.1uf,16V  [402]
C216  47pF  [402]
C452  12pF/0402/50V  [402]
C453  12pF/0402/50V  [402]
C478  0.1uf,16V  [402]
C496  2.2uF,6.3V  [402]
J5  HDR_1x1_M_.1, DNI  [SIP2]
R16  2.2K,1%  [402]
R17  2.2K,1%  [402]
R18  2.2K,1%  [402]
R19  2.2K,1%  [402]
R20  10K,DNI  [402]
R21  10K,1%  [402]
R22  10K,1%  [402]
R23  10K,1%,DNI  [402]
R24  10K,1%  [402]
R26  10K,1%  [402]
R27  10K,1%  [402]
R28  10K,1%  [402]
R29  0,1%  [402]
R30  0,1%  [402]
R214  10K,1%,DNI  [402]
R318  1.74K  [402]
R319  2K  [402]
R322  1.74K,DNI  [402]
R323  2K,DNI  [402]
R407  10K,1%  [402]
R411  10K,1%, DNI  [402]
R421  10K,1%  [402]
R453  10K,1%  [402]
S1  SW PUSH_TH  [SW4_EVQF004R]
TP5  TP  [TP30C12D]
TP7  TP  [TP30C12D]
TP8  TP  [TP30C12D]
TP9  TP  [TP30C12D]
Y9  16.384MHz  [XTAL4_3P2X2P5_SMD]
Y10  16.384MHz  [OSC4_2P5X2P0XP5]
sheet P04_TPS6590376 2, LDO & RTC
BAT1  CR1220MFR FV, DNI  [BATT2_78X492]
C17  2.2uF,6.3V  [402]
C18  2.2uF,6.3V  [402]
C19  2.2uF,6.3V  [402]
C20  2.2uF,6.3V  [402]
C21  2.2uF,6.3V  [402]
C22  2.2uF,6.3V  [402]
C23  10uF,6.3V  [603]
C24  2.2uF,6.3V  [402]
C25  2.2uF,6.3V  [402]
C26  2.2uF,6.3V  [402]
C27  2.2uF,6.3V  [402]
C28  2.2uF,6.3V  [402]
C29  2.2uF,6.3V  [402]
C30  0.1uf,16V  [402]
C31  10pF,50V  [402]
C32  10pF,50V  [402]
C500  2.2uF,6.3V  [402]
C503  0.1uf,16V  [402]
Q9  TRN_2N2907  [SOT23-3]
R32  0,1%  [402]
R33  4.7K  [402]
R416  0,1%  [402]
R423  499,1%  [402]
R424  10K  [402]
R425  40.2K,1%  [402]
R430  DNI  [402]
U6  MCP79410,TFDN  [DFN8_2x3MM]
U43  TLVH431  [SOT23-3]
Y1  CFS206-32.768KDZB  [XTAL_CFS-206]
sheet P05_TPS6590376 3 MPU,DSP SWITCH
C33  4.7uF,6.3V  [402]
C34  47uF,6.3V,1206  [1206]
C35  4.7uF,6.3V  [402]
C36  47uF,6.3V,1206  [1206]
C37  4.7uF,6.3V  [402]
C38  47uF,6.3V,1206  [1206]
C39  4.7uF,6.3V  [402]
C40  47uF,6.3V,1206  [1206]
C41  4.7uF,6.3V  [402]
C42  47uF,6.3V,1206  [1206]
L3  1.0uH,4.2A  [IND130_160X175]
L4  1.0uH,4.2A  [IND130_160X175]
L5  1.0uH,4.2A  [IND130_160X175]
L6  1.0uH,4.2A  [IND130_160X175]
L7  1.0uH,4.2A  [IND130_160X175]
TP13  TP  [TP30C12D]
TP16  TP  [TP30C12D]
TP17  TP  [TP30C12D]
U5  TPS6590376ZWSR  [BGA169_N13_P8]  (sections A,B,C,D,E,F)
sheet P06_TPS6590376 4 CORE & 1.8V
C43  4.7uF,6.3V  [402]
C44  47uF,6.3V,1206  [1206]
C45  4.7uF,6.3V  [402]
C46  4.7uF,6.3V  [402]
C47  47uF,6.3V,1206  [1206]
C48  4.7uF,6.3V  [402]
C50  10uF,6.3V  [603]
C442  10uF,6.3V  [603]
C504  0.1uf,16V  [402]
L8  1.0uH,4.2A  [IND130_160X175]
L9  1.0uH,4.2A  [IND130_160X175]
Q8  TRN_2N2907  [SOT23-3]
R418  499  [402]
R419  10K,1%  [402]
R420  40.2K,1%  [402]
R429  DNI  [402]
TP18  TP  [TP30C12D]
TP19  TP  [TP30C12D]
U35  TLVH431  [SOT23-3]
sheet P07_AM572x CORE POWER & EEPROM
C51  0.1uF/201  [201]
C52  470pF  [201]
C53  10uF,6.3V  [603]
C54  10uF,6.3V  [603]
C55  470pF  [201]
C56  0.22uF/201  [201]
C57  0.1uF/201  [201]
C58  0.1uF/201  [201]
C59  470pF  [201]
C60  0.1uF/201  [201]
C61  0.1uF/201  [201]
C62  0.1uF/201  [201]
C63  2.2uF,6.3V  [402]
C64  4.7uF,6.3V  [402]
C65  470pF  [201]
C66  0.1uF/201  [201]
C67  0.1uF/201  [201]
C68  0.1uF/201  [201]
C69  470pF  [201]
C70  4.7uF,6.3V  [402]
C71  0.1uF/201  [201]
C72  0.1uF/201  [201]
C73  0.1uF/201  [201]
C74  470pF  [201]
C75  470pF  [201]
C76  470pF  [201]
C77  0.1uF/201  [201]
C78  0.22uF/201  [201]
C79  0.47uF/201  [201]
C80  2.2uF,6.3V  [402]
C81  0.1uf,16V  [402]
C82  470pF  [201]
C83  0.1uF/201  [201]
C84  0.1uF/201  [201]
C85  0.1uF/201  [201]
C86  470pF  [201]
C87  470pF  [201]
C88  0.22uF/201  [201]
C89  0.22uF/201  [201]
C90  1uF,4V,0201  [201]
C91  1uF,4V,0201  [201]
C92  2.2uF,6.3V  [402]
C93  22uF,6.3V  [805]
R37  10K,1%  [402]
TP4  TESTPT1  [tp1-8040]
U8  MEM_24WC256_8SOIC  [SOIC_8]
sheet P08_AM572x CLOCKS & RESET
C94  0.1uf,16V  [402]
C95  0.1uF/201  [201]
C96  0.1uF/201  [201]
C97  0.1uf,16V  [402]
C98  0.1uF/201  [201]
C99  0.1uf,16V  [402]
C100  18pF,50V  [402]
C101  18pF,50V  [402]
C102  12pF,50V  [402]
C103  12pF,50V  [402]
C104  0.1uf,16V  [402]
C105  0.1uf,16V  [402]
C108  0.1uf,16V  [402]
C109  220pF,50V  [805]
C110  0.1uf,16V  [402]
C111  0.1uf,16V  [402]
C112  220pF,50V  [805]
C230  DNI  [402]
C476  0.33uf,16V  [402]
C550  0.1uf,16V  [402]
R38  DNI,0402  [402]
R39  0,1%  [402]
R40  DNI,0402  [402]
R41  10K,1%  [402]
R42  10K,1%  [402]
R43  2.2K,1%  [402]
R44  10K,1%  [402]
R45  DNI,0402  [402]
R46  10K,1%  [402]
R47  DNI,0402  [402]
R48  100K,1%  [402]
R49  10K,1%,DNI  [402]
R50  10K,1%  [402]
R51  10K,1%  [402]
R52  10K,1%  [402]
R53  0,1%  [402]
R54  DNI,0402  [402]
R55  0,1%,DNI  [402]
R56  10K,1%  [402]
R57  0,1%  [402]
R58  10K,1%  [402]
R244  0,1%  [402]
R385  DNI  [402]
R395  0,1%  [402]
R404  22.6K,1%  [402]
R405  10K,DNI  [402]
R422  0,1%  [402]
S2  SW PUSH_TH  [SW4_EVQF004R]
U9  SN74LVC1G11DBV  [SC70-6]
U10  SN74LVC1G08DCK  [SC70-5]
U12  TPS_3808G09  [sot23-6]
U13  TPS_3808G33  [sot23-6]
U34  SN74LVC2G132DCU  [U_8_DCU]  (sections A,B)
Y2  20MHz,SMD  [XTAL2_6X3P5_SMD]
Y3  22.5792MHZ  [XTAL4_3P2X2P5_SMD]
sheet P09 AM572x_IO POWER & GND
C113  10uF,6.3V  [603]
C114  0.1uF/201  [201]
C115  0.1uF/201  [201]
C116  0.1uF/201  [201]
C117  470pF  [201]
C118  0.1uF/201  [201]
C119  470pF  [201]
C120  0.1uF/201  [201]
C121  0.1uF/201  [201]
C122  10uF,6.3V  [603]
C123  470pF  [201]
C124  0.1uF/201  [201]
C125  0.1uF/201  [201]
C126  0.1uF/201  [201]
C127  470pF  [201]
C128  470pF  [201]
C129  0.1uF/201  [201]
C130  10uF,6.3V  [603]
C131  10uF,6.3V  [603]
C132  0.1uF/201  [201]
C133  0.1uF/201  [201]
C134  470pF  [201]
C135  0.1uF/201  [201]
C136  0.1uF/201  [201]
C137  470pF  [201]
C138  0.1uF/201  [201]
C139  0.1uF/201  [201]
C140  0.1uF/201  [201]
C141  1uF,4V,0201  [201]
C142  1uF,4V,0201  [201]
C143  1uF,4V,0201  [201]
C144  1uF,4V,0201  [201]
C145  1uF,4V,0201  [201]
C146  1uF,4V,0201  [201]
C147  1uF,4V,0201  [201]
C148  1uF,4V,0201  [201]
C149  1uF,4V,0201  [201]
C150  1uF,4V,0201  [201]
C151  1uF,4V,0201  [201]
C152  1uF,4V,0201  [201]
C153  1uF,4V,0201  [201]
C154  1uF,4V,0201  [201]
C155  1uF,4V,0201  [201]
R417  220,5%  [402]
sheet P10_AM572x  DDR3 POWER, & JTAG
C156  22uF,6.3V  [805]
C157  470pF  [201]
C158  470pF  [201]
C159  0.1uF/201  [201]
C160  0.1uF/201  [201]
C161  0.22uF/201  [201]
C162  470pF  [201]
C163  4.7uF,6.3V  [402]
C164  1uF,4V,0201  [201]
C165  0.22uF/201  [201]
C166  0.22uF/201  [201]
C167  0.22uF/201  [201]
C168  0.22uF/201  [201]
C169  0.1uF/201  [201]
C170  0.1uF/201  [201]
C171  0.22uF/201  [201]
C172  0.22uF/201  [201]
C173  0.1uF/201  [201]
C174  470pF  [201]
C175  0.1uF/201  [201]
C176  470pF  [201]
C177  0.1uF/201  [201]
C178  0.1uF/201  [201]
C179  4.7uF,6.3V  [402]
C180  22uF,6.3V  [805]
C181  0.1uF/201  [201]
C182  0.1uF/201  [201]
C183  470pF  [201]
C184  0.1uF/201  [201]
C185  470pF  [201]
C186  470pF  [201]
C187  0.1uF/201  [201]
C188  470pF  [201]
C189  10uF,6.3V  [603]
C190  10uF,6.3V  [603]
C191  0.1uF/201  [201]
C192  0.1uF/201  [201]
C193  470pF  [201]
C194  0.1uF/201  [201]
C195  0.1uF/201  [201]
C196  0.1uF/201  [201]
C197  .001uf,50V  [402]
C198  0.1uF/201  [201]
C199  0.1uF/201  [201]
C200  0.1uF/201  [201]
C201  470pF  [201]
C202  10uF,6.3V  [603]
C203  0.1uF/201  [201]
C204  0.1uF/201  [201]
C497  10uF,6.3V  [603]
C498  0.1uF/201  [201]
C499  470pF  [201]
C547  0.1uF/201  [201]
C548  470pF  [201]
C549  4.7uF,6.3V  [402]
FB14  BLM15BD182SN1  [402]
L10  FLT_HIFREQ_.47UF  [FLT3SMD_0805-2]
L11  FLT_HIFREQ_.47UF  [FLT3SMD_0805-2]
L24  FLT_HIFREQ_.47UF  [FLT3SMD_0805-2]
P4  20 Pin JTAG  [HEADER10X2_SMD]
R59  4.7K  [402]
R61  22,5%  [402]
R62  4.7K  [402]
R63  22,5%  [402]
R64  22,5%  [402]
R66  4.7K  [402]
sheet P11_AM572x ETHERNET 0
C205  47uF,6.3V,1206  [1206]
C206  4.7uF,6.3V  [402]
C207  0.1uf,16V  [402]
C208  10uF,6.3V  [603]
C209  0.1uf,16V  [402]
C210  10uF,6.3V  [603]
C211  0.1uf,16V  [402]
C212  10uF,6.3V  [603]
C213  0.1uf,16V  [402]
C214  47uF,6.3V,1206  [1206]
C215  DNI  [402]
C217  18pF,50V  [402]
C218  18pF,50V  [402]
C219  10uF,DNI  [603]
C525  0.1uf,16V  [402]
C526  0.1uf,16V  [402]
C527  0.1uf,16V  [402]
C528  .001uF,50V  [402]
C529  .001uF,50V  [402]
C531  0.1uf,16V  [402]
C532  0.1uf,16V  [402]
C533  .001uF,50V  [402]
C534  .001uF,50V  [402]
C535  .001uF,50V  [402]
FB1  150OHM800mA  [805]
FB2  0,1%,0805  [805]
FB3  150OHM800mA  [805]
FB4  150OHM800mA  [805]
P5  LPJG17561BGNL Dual RJ45 10/100/1000  [RJ45_2X1_XFRM_LED]
Q1  FDT434P  [SOT223-1]
R68  220,5%  [402]
R69  220,5%  [402]
R70  1K,5%  [402]
R71  1K,5%  [402]
R72  1K,5%  [402]
R73  1K,5%  [402]
R74  10K,1%  [402]
R75  10K,1%  [402]
R76  10K,1%  [402]
R77  10K,1%  [402]
R78  22,5%  [402]
R79  22,5%  [402]
R80  22,5%  [402]
R81  22,5%  [402]
R82  22,5%  [402]
R83  22,5%  [402]
R84  0,1%  [402]
R85  0,1%  [402]
R86  0,1%  [402]
R87  0,1%  [402]
R88  0,1%  [402]
R89  0,1%  [402]
R90  1K,5%  [402]
R91  1K,5%  [402]
R92  12.1K,1%  [402]
R93  10K,1%  [402]
R94  DNI,0402  [402]
R95  100K,1%,DNI  [402]
R96  0,1%  [402]
R97  220,5%  [402]
R98  220,5%  [402]
R316  0,1%,DNI  [402]
R331  DNI  [402]
R389  4.7K  [402]
U14  KSZ9031RNX  [QFN48]
Y5  25MHz  [xtal_3p2x5smd]
sheet P16_AM572x, AUDIO, & DEBUG
U11  AM5728  [sktbga-zkk-6334-p760]  (sections -1,-10,-11,-12,-13,-14,-15,-16,-17,-18,-19,-2,-3,-4,-5,-6,-7,-8,-9)

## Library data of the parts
C1 C7 = CAP_0.1uF_X7R_25V_10%_0805
C2 C8 C9 = CAP_100UF_TANT_6.3V_3528-21
C3 C14 C438 C439 = CAP_4.7uF_X5R_50V_10%_LESR_1210: Part Number: GRM32ER71E226KE15L
C4 C13 = CAP_8.2nF_X5R_10V_10%_0201
C5 C548 = CAP
C6 C528 C529 C533-C535 = CAP_6.8nF_X7R_50V_10%_0805
C10 = CAP: Part #: 100993-1223R
C11 = CAP_820PF_X5R_50V_10%_0805
C12 = CAP_15PF_NPO_50V_5%_0805
C15 C16 C30 C81 C94 C97 C99 C104 C105 C108 C110 C111 C207 C209 C211 C213 C215 C230 C474 C476 C478 C503 C504 C519 C525-C527 C531 C532 C550 = CAP_0.1uF_X7R_16V_10%_0402
C472 C473 C475 C501 C502 = CAP: Part #: C0402C221K5RACTU
C197 C505 C506 = CAP_0.001_X7R_50V_10%_0402
C516-C518 C521 = CAPACITOR_NON-POL
C33 C35 C37 C39 C41 C43 C45 C46 C48 C64 C70 C163 C179 C206 C520 C549 = CAP_4.7uF_X5R_6.3V_20%_0402
D1 D2 = DIO_ZEN_DDZ9678-7_1.8V
D3 D41 = LED_LTST_C150GKT
F1 = FUSE_4A_QUICK
FB1 FB3 FB4 FB10 FB11 FB14 FB15 = FERRITE_180_800_0805
FL5 = CM2021Y330R-10
J1 = HDR_1x1_M_0.1
L1 L2 = INDUCTOR
MH1-MH5 = TESTPOINT
P1 = CONN_MOD_8-8_J_9
Q11 = 2N2222_0
R2 R13 = RES_10.1K_1_16W_1%_0402
R3 R5 R9 R14 R433 R434 R438 R439 = RESISTOR
R4 R12 R92 = RES_12.1K_1_16W_1%_0402
R6 R11 = RES_20.5K_1_16W_1%_0402
R8 R70-R73 R90 R91 R240 = RES_1K_1_16W_5%_0402
R10 R20-R24 R26 R27 R37 R41 R42 R44 R46 R49-R52 R56 R58 R74-R77 R93 R214 R405 R407 R411 R419-R421 R424 R425 R429 R430 R436 R440 R453 = RES_10K_1_16W_1%_0402
R15 R33 = RES_4.75K_1_16W_1%_0402
R331 R332 R385 R400-R403 = RES_1M_1_16W_1%_0402
U1 U3 = IC_TPS54331,3A_0
U2 = TPS22965DSG_1: Part #: 104267-0001R
U4 = IC_TMP102AIDRL_SOT563
U32 = TC648_0
C216 = CAP_0.1uF_X7R_16V_10%_0402: Part Number: 04025A470JAT2A
C452 C453 = C_12pF_0402_50V_COG_0402: Part #: 101782-1124R
C17-C22 C24-C29 C63 C80 C92 C496 C500 = CAP_2.2uF_X5R_6.3V_10%_0402
J5 = HDR_1x1_M_.1
R16-R19 R43 = RES_2.2K_1_16W_1%_0402
R28 R38 R40 R45 R47 R54 R55 R94 R318 R319 R322 R323 = RES_DNI_1_16W_1%_0402
FB2 R29 R30 R32 R39 R53 R57 R84-R89 R96 R244 R316 R395 R416 R422 = RES_0_1_16W_1%_0402
S1 S2 = SW_PUSH_TH
TP5 TP7-TP9 TP13 TP16-TP19 = TP
Y9 Y10 = CRYS_24MHz_SCC
BAT1 = BATT_HOLD_BH501
C23 C50 C53 C54 C113 C122 C130 C131 C189 C190 C202 C208 C210 C212 C219 C442 C497 = CAP_10uF_X5R_6.3V_20%_0603
C31 C32 = CAP_10PF_COG_50V_5%_0402
Q8 Q9 = TRN_1
R418 R423 = RES_240_1_16W_1%_0402
U6 = IC_MCP79410
U35 U43 = MA735_TO_0
Y1 = CRYS_32_768KHz_SMD
C34 C36 C38 C40 C42 C44 C47 C205 C214 = CAP_47uF_X5R_6.3V_20%_1206
L3-L9 = IND_PWR_1.0uH_4.2A_SMD
U5 = IC_TPS659039_8
C51 C55 C57-C62 C66-C69 C71-C77 C82-C87 C95 C96 C98 C114-C121 C123-C129 C132-C140 C157-C160 C169 C170 C173-C178 C181-C188 C191-C196 C198-C201 C203 C204 C498 C499 C547 = CAP_0.1uF_X5R_6.3V_20%_0201
C52 C56 C78 C88 C89 C161 C162 C165-C168 C171 C172 = CAP_0.22uf_X5R_6.3V_20%_0201
C65 C79 = CAP_0.47UF_X5R_4V_20%_0201
C90 C91 C141-C155 C164 = CAP_1.0UF_X5R_4V_20%_0201
C93 C156 C180 = CAP_22uF_X5R_6.3V_20%_0805
TP4 = TESTPT1
U8 = MEM_24WC256_0
C100-C103 = CAP_18PF_COG_50V_5%_0402
C109 C112 = CAP_220PF_X7R_50V_10%_0402
R48 R95 = RES_100K_1_16W_1%_0402
R404 = RES_22.6K_1_16W_1%_0402
U9 = IC_SN74LVC1G11_DRY
U10 = IC_SN74LVC1G08_DCK
U12 U13 = PWR_TPS3808G09DBVR_SOT23_0
U34 = IC_SN74LVC2G132DCU
Y2 = CRYS_20MHz_12.5pF_2P_3.2x1.5
Y3 = CRYS_22.5792MHz_7pF_4P_3.2x2.5
R68 R69 R97 R98 R417 = RES_220_1_16W_5%_0402
L10 L11 L24 = FLT_HIFREQ_.47UF
P4 = HDR_JTAG_20P
R59 R62 R66 R389 = RES_4.7K_1_16W_5%_0402
R61 R63 R64 R78-R83 = RES_22_1_16W_5%_0402
C217 C218 = CAP_18PF_NPO_50V_5%_0402
P5 = CONN_RJ45_DUAL_GIGABIT_1
Q1 = IRF5210S_SM_0
U14 = IC_KSZ9031RNX_QFN48_9
Y5 = CRYS_25MHz_18pF_2P_5.0x3.2
U11 = IC_AM572x_BGA_34

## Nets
3V3_RC: C11.2 R12.1
5V0: C2.1 C17.2 C20.2 FB15.1 J1.1 L1.2 R2.1 U2.4(VBIAS) U5.A6(LDO12_IN) U5.A9(LDOUSB_IN2) U5.A10(LDO7USB_IN1) ; also on sheet 16 26 27
5V0_COMP: C5.2 R4.1 U1.6(COMP)
5V0_RC: C6.1 R4.2
5V0_SNS: R2.2 R5.2 U1.5(VSNS)
12V: C3.1 C14.1 C438.1 C439.1 C516.1 FB10.2 FL5.3 R3.1 R9.1 R240.1 U1.2(VIN) U3.2(VIN) ; also on sheet 24 26
12V_MAIN: F1.1 P1.1 P1.1A
GND: BAT1.2(-) C2.2 C3.2 C4.2 C5.1 C6.2 C8.2 C9.2 C10.2 C12.2 C13.2 C14.2 C15.2 C16.1 C17.1 C18.1 C19.1 C20.1 C21.1 C22.1 C23.2 C24.1 C25.1 C26.1 C27.1 C28.1 C29.1 C30.2 C31.2 C32.2 C33.2 C34.2 C35.2 C36.2 C37.2 C38.2 C39.2 C40.2 C41.2 C42.2 C43.2 C44.2 C45.2 C46.2 C47.2 C48.2 C50.2 C51.2 C52.1 C53.2 C54.2 C55.1 C56.1 C57.2 C58.1 C59.2 C60.1 C61.2 C62.1 C63.2 C64.2 C65.2 C66.1 C67.1 C68.2 C69.2 C70.2 C71.1 C72.1 C73.2 C74.2 C75.2 C76.2 C77.2 C78.1 C79.2 C80.2 C81.2 C82.2 C83.2 C84.2 C85.2 C86.2 C87.2 C88.1 C89.1 C90.2 C91.2 C92.1 C93.2 C94.2 C95.1 C96.1 C97.2 C98.1 C99.2 C104.2 C105.2 C108.2 C109.2 C110.2 C111.2 C112.2 C113.2 C114.2 C115.2 C116.2 C117.2 C118.2 C119.2 C120.2 C121.2 C122.2 C123.2 C124.2 C125.2 C126.2 C127.2 C128.2 C129.2 C130.2 C131.2 C132.2 C133.2 C134.2 C135.2 C136.2 C137.2 C138.2 C139.2 C140.2 C141.1 C142.2 C143.1 C144.2 C145.1 C146.2 C147.1 C148.2 C149.1 C150.2 C151.1 C152.2 C153.1 C154.2 C155.1 C156.2 C157.2 C158.2 C159.2 C160.2 C161.2 C162.2 C163.2 C164.2 C165.2 C166.2 C167.2 C168.2 C169.2 C170.2 C171.2 C172.2 C173.2 C174.2 C175.2 C176.2 C177.2 C178.2 C179.2 C180.2 C181.2 C182.2 C183.2 C184.2 C185.2 C186.2 C187.2 C188.2 C189.2 C190.2 C191.2 C192.2 C193.2 C194.2 C195.2 C196.2 C197.2 C198.2 C199.2 C200.2 C201.2 C202.2 C203.2 C204.2 C205.2 C206.2 C207.2 C208.2 C209.1 C210.2 C211.2 C212.2 C213.1 C214.2 C215.1 C216.1 C217.1 C218.1 C219.2 C230.1 C438.2 C439.2 C442.2 C452.2 C453.2 C472.1 C473.1 C474.1 C475.1 C478.2 C496.2 C497.2 C498.2 C499.2 C500.1 C501.1 C503.2 C504.2 C505.2 C506.2 C516.2 C518.2 C519.2 C520.2 C521.1 C525.2 C526.2 C527.2 C528.2 C529.2 C531.2 C532.2 C533.2 C534.2 C535.2 C547.2 C548.2 C549.2 C550.2 D1.2(ANODE) D2.2(ANODE) D3.1(C) D41.1(C) FB11.2 FL5.4 L10.2 L11.2 L24.2 MH5.1(TP) P4.4(TDIS) P4.8(GND.1) P4.10(GND.2) P4.12(GND.3) P4.16(GND.4) P4.20(GND.5) P5.10 P5.20 Q11.2(EMITTER) R5.1 R6.2 R11.2 R12.2 R14.1 R21.2 R22.2 R24.2 R26.2 R27.2 R28.1 R43.2 R47.2 R49.2 R50.2 R51.2 R54.1 R58.2 R66.2 R72.1 R73.1 R91.2 R92.1 R244.2 R319.1 R323.1 R331.1 R385.1 R395.2 R400.1 R401.1 R402.1 R403.1 R404.2 R411.2 R416.2 R417.2 R421.2 R422.2 R436.2 R439.2 S1.1(A) S2.1(A) U1.7(GND) U1.9(PAD) U2.5(GND) U2.9(PWR_PAD) U3.7(GND) U3.9(PAD) U4.2(GND) U4.4(ADD0) U5.A1(SUB_GND) U5.A4(REFGND1) U5.A7(GNDANA) U5.A13(SUB_GND) U5.B2(GPADC_IN0) U5.B8(SYNC_TO_EXCLOCK) U5.B10(SUB_GND) U5.B11(SUB_GND) U5.C2(GPADC_IN1) U5.C3(GPADC_IN2) U5.C12(SMPS12_FBK_GND) U5.D4(SMPS7_GND_1) U5.D5(SMPS7_GND_2) U5.D6(SUB_GND) U5.D7(SUB_GND) U5.D10(SMPS1_GND_1) U5.E4(SMPS7_GND_3) U5.E7(VAC/ACOK) U5.E8(SUB_GND) U5.E9(SMPS1_GND_2) U5.E10(SMPS1_GND_3) U5.F4(SMPS4_GND_1) U5.F5(AGND.1) U5.F6(SUB_GND) U5.F7(SUB_GND) U5.F9(SMPS2_GND_1) U5.F10(SMPS2_GND_2) U5.G4(SMPS4_GND_2) U5.G5(SMPS4_GND_3) U5.G7(SUB_GND) U5.G10(SMPS2_GND_3) U5.H4(SMPS5_GND_1) U5.H5(SMPS5_GND_2) U5.H6(SUB_GND) U5.H7(SUB_GND) U5.H10(SMPS3_GND_1) U5.J4(SMPS5_GND_3) U5.J6(SUB_GND) U5.J9(SMPS3_GND_2) U5.J10(SMPS3_GND_3) U5.K3(SMPS45_FDBK_GND) U5.L5(SMPS6_GND) U5.L6(SMPS6_GND_1) U5.L7(SMPS9_GND) U5.L8(SMPS9_GND_1) U5.L9(SMPS8_GND_1) U5.L10(SMPS8_GND) U5.M1(SUB_GND) U5.M2(SUB_GND) U5.M12(GND_DIG) U5.M13(AGND.2) U5.N1(SUB_GND) U5.N2(VIO_GND) U5.N13(SUB_GND) U6.4(VSS) U8.1(A0) U8.2(A1) U8.3(NC) U8.4(VSS) U9.2(GND) U10.3(GND) U11.A1(VSS.9) U11.A2(VSS.11) U11.A6(VSS.15) U11.A14(VSS.41) U11.A23(VSS.68) U11.A28(VSS.79) U11.AA8(VSS.17) U11.AA9(VSS.19) U11.AA10(VSS.14) U11.AA14(VSS.48) U11.AA15(VSS.51) U11.AA20(VSS.61) U11.AB14(VSS.40) U11.AB20(VSS.60) U11.AD1(VSS.3) U11.AD24(VSS.70) U11.AG1(VSS.2) U11.AH1(VSS.1) U11.AH2(VSS.10) U11.AH8(VSS.53) U11.AH20(VSS.52) U11.AH28(VSS.75) U11.B1(VSS.8) U11.D13(VSS.39) U11.D19(VSS.59) U11.E13(VSS.38) U11.E19(VSS.58) U11.F1(VSS.7) U11.F7(VSS.54) U11.G7(VSS.57) U11.G8(VSS.65) U11.G9(VSS.66) U11.H12(VSS.33) U11.J12(VSS.32) U11.J15(VSS.XX) U11.J28(VSS.78) U11.K1(VSS.6) U11.K4(VSS.12) U11.K5(VSS.13) U11.K15(VSS.28) U11.K24(VSS.55) U11.K25(VSS.56) U11.L13(VSS.37) U11.L14(VSS.46) U11.M19(VSS.69) U11.N14(VSS.X5) U11.N15(VSS.16) U11.N19(VSS.18) U11.N24(VSS.72) U11.N25(VSS.74) U11.P28(VSS.77) U11.R1(VSS.5) U11.R12(VSS.29) U11.R13(VSS.X6) U11.R15(VSS.43) U11.R21(VSS.64) U11.T10(VSS.21) U11.T11(VSS.26) U11.T12(VSS.23) U11.T14(VSS.X7) U11.T15(VSS.42) U11.T17(VSS.47) U11.T18(VSS.24) U11.T21(VSS.27) U11.U14(VSSA_VIDEO) U11.U15(VSS.X8) U11.U17(VSS.X9) U11.U20(VSS.62) U11.U21(VSS.63) U11.V15(VSS.30) U11.V17(VSS.X10) U11.W1(VSS.4) U11.W15(VSS.36) U11.W24(VSS.71) U11.W25(VSS.73) U11.W28(VSS.76) U12.2(GND) U13.2(GND) U14.29(VSS) U14.49(P_GND) U32.3(VAS) U32.4(GND) U34.4(GND) Y9.2(NC0) Y9.4(NC1) Y10.2(NC0) Y10.4(NC1) ; also on sheet 12 13 14 15 16 17 18 19 20 21 22 23 24 25 26 27
GND_EARTH: C215.2 C216.2 C230.2 C472.2 C473.2 C474.2 C475.2 C501.2 C502.2 MH1.1(TP) MH2.1(TP) MH3.1(TP) MH4.1(TP) P1.SHLD1 P1.SHLD2 P5.SHLD1 P5.SHLD2 R331.2 R332.2 R385.2 R400.2 R401.2 R402.2 R403.2 S1.3(B) S1.4(BB) S2.3(B) S2.4(BB) ; also on sheet 14 15 16 17 24
VBUS_DET: U5.C13(GPIO_1/VBUSDET) ; also on sheet 13
VCC_SENSE: R30.2 U5.B3(VCC_SENSE)
VCC_SENSE2: R29.2 U5.A11(VCC_SENSE2)
VDD_1V8: C47.1 C185.1 C186.1 C187.1 C188.1 C189.1 C190.1 C191.1 C192.1 C193.1 C194.1 C195.1 C196.1 C503.1 C504.1 L9.2 Q8.3(COLLECTOR) Q9.3(COLLECTOR) R420.2 R425.2 TP19.1 U5.L11(SMPS8_FDBK) U11.AA7(VDDS_MLBP.1) U11.AA18(VDDS18V_DDR1.1) U11.AA19(VDDS18V_DDR1.2) U11.G18(VDDS18V.8) U11.H17(VDDS18V.11) U11.J21(VDDS18V_DDR2.3) U11.J22(VDDS18V_DDR2.4) U11.M8(VDDS18V.9) U11.M9(VDDS18V.7) U11.N8(VDDS18V.4) U11.N21(VDDS18V_DDR2.2) U11.P8(VDDS18V.5) U11.P20(VDDS18V_DDR2.5) U11.P21(VDDS18V_DDR2.1) U11.R8(VDDS18V.3) U11.T8(VDDS18V.2) U11.V21(VDDS18V.12) U11.V22(VDDS18V.6) U11.W17(VDDS18V.10) U11.W18(VDDS18V.1) U11.W21(VDDS18V_DDR1.4) U11.Y7(VDDS_MLBP.2) U11.Y21(VDDS18V_DDR1.3) U35.3(ANODE) U43.3(ANODE) ; also on sheet 25
VDD_3V3: C15.1 C30.1 C50.1 C81.1 C113.1 C114.1 C115.1 C116.1 C117.1 C118.1 C119.1 C120.1 C121.1 C122.1 C123.1 C124.1 C125.1 C126.1 C127.1 C128.1 C129.1 C130.1 C131.1 C132.1 C133.1 C134.1 C135.1 C136.1 C137.1 C138.1 C139.1 FB3.1 P4.5(TVD) Q8.2(EMITTER) R8.1 R15.1 R16.1 R17.1 R18.1 R19.1 R32.1 R33.1 R37.2 R38.2 R45.1 R46.1 R48.1 R59.1 R62.1 R68.2 R69.2 R97.2 R98.2 R389.1 R418.1 R419.1 U2.7(VOUT.2) U2.8(VOUT.1) U4.5(V+) U5.D9(VIO_IN) U6.8(VCC) U8.8(VCC) U11.AB6(VDDSHV7.1) U11.AB7(VDDSHV7.2) U11.AD5(VDDSHV6.2) U11.AD7(VDDSHV6.4) U11.AE7(VDDSHV6.3) U11.AF5(VDDSHV6.1) U11.B6(VDDSHV2.1) U11.B23(VDDSHV3.9) U11.C24(VDDSHV4.1) U11.D10(VDDSHV2.5) U11.D16(VDDSHV3.4) U11.D22(VDDSHV3.8) U11.E3(VDDSHV1.1) U11.E5(VDDSHV1.4) U11.E10(VDDSHV2.4) U11.E16(VDDSHV3.3) U11.E22(VDDSHV3.7) U11.G4(VDDSHV1.2) U11.G5(VDDSHV1.3) U11.G15(VDDSHV3.2) U11.H8(VDDSHV1.5) U11.H9(VDDSHV1.6) U11.H10(VDDSHV2.2) U11.H11(VDDSHV2.3) U11.H15(VDDSHV3.1) U11.H16(VDDSHV3.6) U11.H18(VDDSHV3.5) U11.H19(VDDSHV3.10) U11.J8(VDDSHV11.2) U11.K8(VDDSHV11.1) U11.N4(VDDSHV10.2) U11.N5(VDDSHV10.4) U11.P10(VDDSHV10.6) U11.R7(VDDSHV10.5) U11.R10(VDDSHV10.7) U11.T4(VDDSHV10.1) U11.T5(VDDSHV10.3) U11.U10(VDDSHV9.3) U11.W4(VDDSHV9.1) U11.W5(VDDSHV9.2) ; also on sheet 12 13 14 15 16 17 23 24 25 26 27
VDD_3V3_ON: R10.2 R436.1 U2.3(ON) U5.F8(REGEN1)
VDD_3V3_SP: C94.1 C97.1 C104.1 R32.2 R41.1 R42.1 R44.1 R52.1 R405.1 U9.5(VCC) U10.5(VCC) U12.6(VDD) U34.8(VCC)
VDD_CORE: C44.1 C54.1 C55.2 C56.2 C58.2 C60.2 C62.2 C65.1 C66.2 C67.2 C71.2 C72.2 L8.2 TP18.1 U5.K6(SMPS6_FBK) U11.H13(VDD.18) U11.H14(VDD.22) U11.J17(VDD.X1) U11.J18(VDD.X2) U11.L7(VDD.34) U11.L8(VDD.15) U11.N10(VDD.6) U11.N13(VDD.16) U11.P11(VDD.9) U11.P12(VDD.12) U11.P13(VDD.X3) U11.R11(VDD.8) U11.R16(VDD.26) U11.R19(VDD.27) U11.T13(VDD.13) U11.T16(VDD.25) U11.T19(VDD.X7) U11.U8(VDD.29) U11.U9(VDD.2) U11.U13(VDD.3) U11.U16(VDD.X8) U11.V8(VDD.1) U11.V16(VDD.X9)
VDD_DDR: C38.1 C156.1 C157.1 C158.1 C159.1 C160.1 C161.1 C162.1 C163.1 C164.1 C165.1 C166.1 C167.1 C168.1 C169.1 C170.1 C171.1 C172.1 C173.1 C174.1 C175.1 C176.1 C177.1 C178.1 C179.1 C180.1 C181.1 C182.1 C183.1 C184.1 L5.2 TP16.1 U5.K13(SMPS3_FDBK) U11.AA21(VDDS_DDR1.4) U11.AA22(VDDS_DDR1.2) U11.AB21(VDDS_DDR1.3) U11.AB22(VDDS_DDR1.7) U11.AB24(VDDS_DDR1.10) U11.AB25(VDDS_DDR1.11) U11.AC22(VDDS_DDR1.6) U11.AD26(VDDS_DDR1.12) U11.AG20(VDDS_DDR1.9) U11.AG28(VDDS_DDR1.5) U11.AH27(VDDS_DDR1.13) U11.E24(VDDS_DDR2.9) U11.G22(VDDS_DDR2.5) U11.G23(VDDS_DDR2.6) U11.H20(VDDS_DDR2.1) U11.H21(VDDS_DDR2.11) U11.H22(VDDS_DDR2.4) U11.J27(VDDS_DDR2.12) U11.L20(VDDS_DDR2.8) U11.L21(VDDS_DDR2.3) U11.M20(VDDS_DDR2.13) U11.M21(VDDS_DDR2.2) U11.T24(VDDS_DDR2.7) U11.T25(VDDS_DDR2.10) U11.W16(VDDS_DDR1.1) U11.W27(VDDS_DDR1.8) ; also on sheet 18 20 21 22 23
VDD_DSP: C40.1 C42.1 C51.1 C52.2 C53.1 C57.1 C59.1 C61.1 C63.1 C64.1 C68.1 C69.1 C70.1 C73.1 C74.1 C75.1 C76.1 C78.2 C79.1 C80.1 L6.2 L7.2 TP17.1 U5.K2(SMPS45_FDBK) U11.J13(VDD_DSP.7) U11.K10(VDD_DSP.8) U11.K11(VDD_DSP.9) U11.K12(VDD_DSP.10) U11.K13(VDD_DSP.11) U11.L10(VDD_DSP.2) U11.L11(VDD_DSP.4) U11.L12(VDD_DSP.12) U11.M10(VDD_DSP.1) U11.M11(VDD_DSP.5) U11.M12(VDD_DSP.3) U11.M13(VDD_DSP.6) U11.U11(VDD_GPU.5) U11.U12(VDD_GPU.6) U11.U18(VDD_IVA.1[ECO]) U11.U19(VDD_IVA.2[ECO]) U11.V10(VDD_GPU.2) U11.V11(VDD_GPU.3) U11.V14(VDD_GPU.7) U11.V18(VDD_IVA.3[ECO]) U11.V19(VDD_IVA.4[ECO]) U11.W10(VDD_GPU.1) U11.W11(VDD_GPU.4) U11.W13(VDD_GPU.8)
VDD_MPU: C34.1 C36.1 C77.1 C82.1 C83.1 C84.1 C85.1 C86.1 C87.1 C88.2 C89.2 C90.1 C91.1 C92.2 C93.1 C550.1 L3.2 L4.2 R54.2 TP13.1 U5.B13(SMPS12_FBK) U11.K17(VDD_MPU.10) U11.K18(VDD_MPU.2) U11.L15(VDD_MPU.11) U11.L16(VDD_MPU.12) U11.L17(VDD_MPU.6) U11.L18(VDD_MPU.8) U11.L19(VDD_MPU.3) U11.M15(VDD_MPU.13) U11.M16(VDD_MPU.14) U11.M17(VDD_MPU.5) U11.M18(VDD_MPU.7) U11.N17(VDD_MPU.4) U11.N18(VDD_MPU.1) U11.P17(VDD_MPU.15) U11.P18(VDD_MPU.9) U11.R18(VDD_MPU.16) U12.5(SENSE1)
VDD_RTC: C28.2 C108.1 U5.A5(LDO9_OUT) U11.AB15(VDD_RTC)
VDD_SD: C21.2 C140.1 U5.C6(LDO1_OUT) U11.W8(VDDSHV8.2) U11.Y8(VDDSHV8.1) ; also on sheet 17
VDD_SHV5: C22.2 C105.1 Q9.2(EMITTER) R423.1 R424.1 U5.B6(LDO2_OUT) U11.V12(VDDSHV5)
VDDA_1V8_PHYA: C24.2 L11.3 U5.K11(LDO3_OUT) ; also on sheet 14
VDDA_1V8_PHYB: C500.2 FB14.2 L24.3 U5.K12(LDO4_OUT)
VDDA_1V8_PLL: C29.2 C99.1 L10.1 U5.B5(LDOLN_OUT) U11.AD16(VDDA_OSC.1) U11.AE16(VDDA_OSC.2)
VSSA_OSC0: C100.2 C101.2 R244.1 U11.AF15(VSSA_OSC0)
VSSA_OSC1: C102.2 C103.2 R395.1 U11.AC14(VSSA_OSC1) Y3.2(NC0) Y3.4(NC1)
AM_CAP0: C141.2 U11.Y15(CAP_VDDRAM_CORE3)
AM_CAP1: C143.2 U11.J19(CAP_VDDRAM_CORE2)
AM_CAP2: C145.2 U11.P19(CAP_VDDRAM_CORE4)
AM_CAP3: C147.2 U11.Y16(CAP_VDDRAM_CORE5)
AM_CAP4: C149.2 U11.K9(CAP_VBBLDO_DSP)
AM_CAP5: C151.2 U11.J9(CAP_VDDRAM_DSP2)
AM_CAP6: C153.2 U11.K19(CAP_VDDRAM_MPU2)
AM_CAP7: C155.2 U11.L9(CAP_VDDRAM_CORE1)
AM_CAP8: C142.1 U11.R20(CAP_VBBLDO_IVA)
AM_CAP9: C144.1 U11.Y14(CAP_VBBLDO_GPU)
AM_CAP10: C146.1 U11.J16(CAP_VBBLDO_MPU)
AM_CAP11: C148.1 U11.J10(CAP_VDDRAM_DSP)
AM_CAP12: C150.1 U11.T20(CAP_VDDRAM_IVA)
AM_CAP13: C152.1 U11.Y13(CAP_VDDRAM_GPU)
AM_CAP14: C154.1 R417.1 U11.K16(CAP_VDDRAM_MPU1)
AUXFAN_EN: R24.1 R440.1 U5.A12(GPIO_2/REGEN2)
BU_BATT,                            DNI: BAT1.1(+) R416.1 U6.3(VBAT)
CPU_NMIn: R46.2 R47.1 U11.D21(NMIN)
CPU_POR_RESETn: R41.2 R53.2 U9.6(C)
CPU_RESETn: R42.2 R55.1 U10.1(B)
E0_AVDDL: C210.1 C211.1 FB2.2 U14.4(AVDDL2) U14.9(AVDDL1)
E0_DVDDL: C212.1 C213.2 C531.1 C532.1 C533.1 C534.1 C535.1 FB4.2 U14.14(DVDDL1) U14.18(DVDDL5) U14.23(DVDDL4) U14.26(DVDDL6) U14.30(DVDDL2) U14.39(DVDDL3)
E0_GRN: P5.D5 R90.1 U14.17(LED1_/_PME_N1)
E0_ISET: R92.2 U14.48(ISET)
E0_PLL: C208.1 C209.2 FB1.2 U14.44(AVDDL_PLL)
E0_RST: C219.1 R95.2 R96.2 R316.2 U14.42(RESET_N)
E0_XI: C217.2 R94.2 U14.46(XI) Y5.2(NC0)
E0_XO: C218.2 R94.1 U14.45(XO) Y5.1
E0_YEL: P5.D7 R91.1 U14.15(LED2)
E1_GRN: P5.D1 ; also on sheet 12
E1_YEL: P5.D3 ; also on sheet 12
EEWP: R37.1 TP4.1(TP) U8.7(WP)
EMAC(0)_RXD0: R80.1 U11.W2(EMAC(0)_RXD0)
EMAC(0)_RXD1: R81.1 U11.Y2(EMAC(0)_RXD1)
EMAC(0)_RXD2: R82.1 U11.V3(EMAC(0)_RXD2)
EMAC(0)_RXD3: R83.1 U11.V4(EMAC(0)_RXD3)
EMAC[0]_RXC: R79.1 U11.U5(EMAC(0)_RXC)
EMAC[0]_RXCTL: R78.1 U11.V5(EMAC(0)_RXCTL)
EMAC[0]_TXC: R85.1 U11.W9(EMAC(0)_TXC)
EMAC[0]_TXCTL: R84.1 U11.V9(EMAC(0)_TXCTL)
EMAC[0]_TXD0: R86.1 U11.U6(EMAC(0)_TXD0)
EMAC[0]_TXD1: R87.1 U11.V6(EMAC(0)_TXD1)
EMAC[0]_TXD2: R88.1 U11.U7(EMAC(0)_TXD2)
EMAC[0]_TXD3: R89.1 U11.V7(EMAC(0)_TXD3)
EMU0: P4.13(EMU0) R59.2 U11.G21(EMU0)
EMU1: P4.14(EMU1) R62.2 U11.D24(EMU1)
EMU_RSTn: P4.15(SRST) R44.2 U10.2(A)
ENET0_INTn: R389.2 U14.38(INT_N_/_PME_N2) ; also on sheet 27
ENET_PORZ: R39.2 R40.2 R96.1 ; also on sheet 12
ETH0_1.2V: C206.1 C207.1 FB1.1 FB2.1 FB4.1 Q1.2(D1) Q1.4(D2)
ETH0_3V3: C205.1 C214.1 C525.1 C526.1 C527.1 C528.1 C529.1 FB3.2 Q1.3(S) R70.1 R71.1 R74.1 R75.1 R76.1 R77.1 R90.2 R93.2 R95.1 U14.1(AVDDH1) U14.12(AVDDH2) U14.16(DVDDH5) U14.34(DVDDH3) U14.40(DVDDH4)
ETH0_LDO: Q1.1(G) U14.43(LDO_O)
ETH_RESETn: R316.1 U11.U3(GPIO3_17) ; also on sheet 12
EXT_WAKE: R33.2 R49.1 U6.7(MFP) U11.AC16(WAKEUP3) ; also on sheet 26
I2C1_SCL: R17.2 U4.1(SCL) U5.L1(I2C1_SCL_SCK) U8.6(SCL) ; also on sheet 15 27
I2C1_SDA: R16.2 U4.6(SDA) U5.L2(I2C1_SDA_SDI) U8.5(SDA) ; also on sheet 15 27
I2C3_SCL: U6.6(SCL) ; also on sheet 14 27
I2C3_SDA: U6.5(SDA) ; also on sheet 14 27
J3-D6: P5.D6 R69.1
J3-D8: P5.D8 R68.1
J3_D2: P5.D2 R98.1
J3_D4: P5.D4 R97.1
LDO_VRTC: C19.2 C110.1 J5.2 R20.2 R23.1 R56.1 R214.2 R453.1 U5.A8(LDOVRTC_OUT) U11.AB13(VDDA_RTC)
MDIO_CLK: R71.2 U11.V1(MDIO_MCLK) U14.36(MDC) ; also on sheet 12
MDIO_DATA: R70.2 U11.U4(MDIO_DATA) U14.37(MDIO) ; also on sheet 12
OSC0_XI: C101.1 U11.AE15(XI_OSC0) Y2.1
OSC0_XO: C100.1 U11.AD15(X0_OSC0) Y2.2(NC0)
OSC1_XI: C103.1 U11.AC15(XI_OSC1) Y3.1
OSC1_XO: C102.1 U11.AC13(XO_OSC1) Y3.3
P0_TRD[0]N: P5.12 U14.3(TXRXM_A)
P0_TRD[0]P: P5.11 U14.2(TXRXP_A)
P0_TRD[1]N: P5.14 U14.6(TXRXM_B)
P0_TRD[1]P: P5.13 U14.5(TXRXP_B)
P0_TRD[2]N: P5.16 U14.8(TXRXM_C)
P0_TRD[2]P: P5.15 U14.7(TXRXP_C)
P0_TRD[3]N: P5.18 U14.11(TXRXM_D)
P0_TRD[3]P: P5.17 U14.10(TXRXP_D)
P1_TRD[0]N: P5.2 ; also on sheet 12
P1_TRD[0]P: P5.1 ; also on sheet 12
P1_TRD[1]N: P5.4 ; also on sheet 12
P1_TRD[1]P: P5.3 ; also on sheet 12
P1_TRD[2]N: P5.6 ; also on sheet 12
P1_TRD[2]P: P5.5 ; also on sheet 12
P1_TRD[3]N: P5.8 ; also on sheet 12
P1_TRD[3]P: P5.7 ; also on sheet 12
PMIC_BOOT0: R20.1 R21.1 U5.L3(BOOT0)
PMIC_BOOT1: R22.1 R214.1 U5.K7(BOOT1)
PMIC_GPIO_0: R421.1 U5.B12(GPIO_0)
PMIC_GPIO_3: R26.1 U5.H9(GPIO_3)
PMIC_GPIO_5: R27.1 U5.C10(GPIO_5/CLK32KGO)
PMIC_INT: R48.2 U5.K1(INT) U11.AD17(WAKEUP0)
PMIC_OFF: R45.2 R322.1 U11.Y11(ON_OFF)
PMIC_POWERGOOD: TP5.1 U5.J7(POWERGOOD)
PMIC_POWERHOLD: J5.1 R23.2 R28.2 U5.G9(GPIO_7/POWERHOLD)
PMIC_RESET_IN: R56.2 U5.K9(RESET_IN) U13.1(~{RESE}T)
PMIC_RESET_OUT: U5.G6(RESET_OUT) U9.1(A)
PMIC_SCE: R19.2 U5.M3(I2C2_SCL_SCE)
PMIC_SDO: R18.2 U5.H8(I2C2_SDA_SDO)
PMIC_XTAL_IN: C452.1 U5.A3(OSC16MIN) Y9.3 Y10.3
PMIC_XTAL_OUT: C453.1 U5.A2(OSC16MOUT) Y9.1 Y10.1
POR_CT: C109.1 U12.4(CT)
PORz: C95.2 C96.2 R39.1 R57.1 U9.4(Y) U11.AB17(RTC_PORZ) U11.F22(PORZ)
PS_3V3: C8.1 C9.1 C23.1 C26.2 C27.2 C33.1 C35.1 C37.1 C39.1 C41.1 C43.1 C45.1 C46.1 C48.1 C111.1 C442.1 L2.2 R10.1 R13.1 R29.1 R30.1 R58.1 R407.1 U2.1(VIN.1) U2.2(VIN.2) U5.C4(LDO9_IN) U5.C5(LDOLN_IN) U5.C7(VCC1) U5.D11(SMPS1_IN_1) U5.D12(SMPS1_IN_2) U5.D13(SMPS1_IN_3) U5.E1(SMPS7_IN_B1_1) U5.E2(SMPS7_IN_B1_2) U5.E3(SMPS7_IN_B1_3) U5.F1(SMPS4_IN_1) U5.F2(SMPS4_IN_2) U5.F3(SMPS4_IN_3) U5.G11(SMPS2_IN_1) U5.G12(SMPS2_IN_2) U5.G13(SMPS2_IN_3) U5.H11(SMPS3_IN_1) U5.H12(SMPS3_IN_2) U5.H13(SMPS3_IN_3) U5.J1(SMPS5_IN_1) U5.J2(SMPS5_IN_2) U5.J3(SMPS5_IN_3) U5.L12(LDO34_IN) U5.L13(LDO34_IN_1) U5.M4(NC6) U5.M6(SMPS6_IN) U5.M8(SMPS9_IN) U5.M9(SMPS8_IN) U5.N3(NC7) U5.N4(NC8) U5.N6(SMPS6_IN_1) U5.N8(SMPS9_IN_1) U5.N9(SMPS8_IN_1) U13.5(SENSE1) U13.6(VDD) ; also on sheet 23
PS_3V3_COMP: C11.1 C12.1 U3.6(COMP)
PS_3V3_EN: R9.2 R11.1 U3.3(EN)
PS_3V3_SNS: R13.2 R14.2 U3.5(VSNS)
PS_3V3_SS: C13.1 U3.4(SS)
PWRON: C478.1 R407.2 S1.2(AA) U5.G8(PWRON) ; also on sheet 26
R_3V3LED: D3.2(A) R8.2
R_12VLED: D41.2(A) R240.2
R_EMAC[0]_RXC: R72.2 R79.2 U14.35(RX_CLK)
R_EMAC[0]_RXCTL: R73.2 R78.2 U14.33(RX_DV)
R_EMAC[0]_RXD0: R74.2 R80.2 U14.32(RXD0)
R_EMAC[0]_RXD1: R75.2 R81.2 U14.31(RXD1)
R_EMAC[0]_RXD2: R76.2 R82.2 U14.28(RXD2)
R_EMAC[0]_RXD3: R77.2 R83.2 U14.27(RXD3)
R_EMAC[0]_TXC: R85.2 U14.24(GTX_CLK)
R_EMAC[0]_TXCTL: R84.2 U14.25(TX_EN)
R_EMAC[0]_TXD0: R86.2 U14.19(TXD0)
R_EMAC[0]_TXD1: R87.2 U14.20(TXD1)
R_EMAC[0]_TXD2: R88.2 U14.21(TXD2)
R_EMAC[0]_TXD3: R89.2 U14.22(TXD3)
RESETIN: R52.2 S2.2(AA) U12.3(~{MR}) ; also on sheet 26
RSTOUTn: R38.1 R40.1 R43.1 R318.1 U11.F23(RSTOUTN) U34.2(2B) ; also on sheet 15 17 25 26
RTC_ISO: R57.2 U11.AF14(RTC_ISO)
RTC_X1: C32.1 U6.1(X1) Y1.2
RTC_X2: C31.1 U6.2(X2) Y1.1
RTCK: P4.9(TCKRTN) R63.2
RTCKR: R63.1 U11.E18(RTCK)
SW1: L3.1 U5.E11(SMPS1_SW_1) U5.E12(SMPS1_SW_2) U5.E13(SMPS1_SW_3)
SW2: L4.1 U5.F11(SMPS2_SW_1) U5.F12(SMPS2_SW_2) U5.F13(SMPS2_SW_3)
SW3: L5.1 U5.J11(SMPS3_SW_1) U5.J12(SMPS3_SW_2) U5.J13(SMPS3_SW_3)
SW4: L6.1 U5.G1(SMPS4_SW_1) U5.G2(SMPS4_SW_2) U5.G3(SMPS4_SW_3)
SW5: L7.1 U5.H1(SMPS5_SW_1) U5.H2(SMPS5_SW_2) U5.H3(SMPS5_SW_3)
SW6: L8.1 U5.M5(SMPS6_SW_1) U5.N5(SMPS6_SW)
SW9: L9.1 U5.M10(SMPS8_SW) U5.N10(SMPS8_SW_1)
TCK: R64.1 U11.E20(TCLK)
TCLK: P4.11(TCLK) R64.2
TDI: P4.3(TDI) U11.D23(TDI)
TDO: P4.7(TDO) R61.2
TDOR: R61.1 U11.F19(TDO)
TESTV: TP9.1 U5.N12(VPROG/TESTV)
TMP102_ALERT: R15.2 U4.3(ALERT) ; also on sheet 27
TMS: P4.1(TMS) U11.F18(TMS)
TPS_ENABLE1: TP7.1 U5.J5(ENABLE1)
TPS_PWRDOWN: TP8.1 U5.K8(PWRDOWN)
TPS_RST: R53.1 R55.2 U12.1(~{RESE}T)
TRSTN: P4.2(TRSTn) R66.1 U11.D20(TRSTN)
U1-1: C1.2 U1.1(BOOT)
U1-3: R3.2 R6.1 U1.3(EN)
U1-4: C4.1 U1.4(SS)
U1-8: C1.1 D1.1(CATHODE) L1.1 R433.1 U1.8(PH)
U2-6: C10.1 U2.6(CT)
U3-1: C7.2 U3.1(BOOT)
U3-8: C7.1 D2.1(CATHODE) L2.1 R434.1 U3.8(PH)
U5_C8: C25.2 U5.C8(LDOVANA_OUT)
U13-4: C112.1 U13.4(CT)
U14_41: R93.1 U14.41(CLK125_NDO)
USB2_VBUS: R411.1 U5.D8(VBUS) ; also on sheet 14
VBG: C16.2 U5.B7(VBG)
VUSB_3V3: C18.2 U5.B9(LDOUSB_OUT) ; also on sheet 14
WAKEUP1: R50.1 U11.AC17(WAKEUP1)
WAKEUP2: R51.1 U11.AB16(WAKEUP2)
N23410845: C98.2 U10.4(Y) U11.E23(RESETN)
N23730763: C197.1 C198.1 C199.1 C200.1 C203.1 L10.3 U11.M14(VDDA_ABE_PER) U11.N11(VDDA_DEBUG) U11.N12(VDDA_DSP) U11.N16(VDDA_MPU) U11.P14(VDDA_VIDEO) U11.P15(VDDA_GMAC_CORE) U11.P16(VDDA_DDR) U11.R14(VDDA_GPU) U11.R17(VDDA_IVA)
N24165486: C201.1 C202.1 C204.1 L11.1 U11.V13(VDDA_SATA) U11.W12(VDDA_USB3)
N26024435: C497.1 C498.1 C499.1 L24.1 U11.AA16(VDDA_PCIE1) U11.AA17(VDDA_PCIE0) U11.W14(VDDA_PCIE)
N26024442: C547.1 C548.1 C549.1 FB14.1 U11.Y17(VDDA_HDMI)
N28613451: R318.2 R319.2 U5.E6(NRESWARM)
N28614009: R322.2 R323.2 R453.2 U5.E5(NSLEEP)
N29245750: R422.1 U11.AE14(RTC_OSC_XI_CLKIN32)
N29286052: R405.2 U9.3(B) U34.1(2A) U34.3(2Y)
N29286254: C476.1 U34.7(2Y)
N29286257: C476.2 R404.1 U34.5(2A) U34.6(2B)
N29975844: C496.1 U5.C1(OSC16MCAP)
N30273551: R419.2 R420.1 R429.2 U35.1(REF)
N30284852: Q8.1(BASE) R418.2 R429.1 U35.2(CATHODE)
N30391816: Q9.1(BASE) R423.2 R430.1 U43.2(CATHODE)
N30391875: R424.2 R425.1 R430.2 U43.1(REF)
N30585990: C505.1 R433.2
N30586350: C506.1 R434.2
N30602906: C517.1 F1.2 FB10.1 FL5.2
N30602912: C502.1 C517.2 FB11.1 FL5.1 P1.2 P1.2A R332.1
N30648931: C518.1 U32.2(CF)
N30648941: C519.1 C520.1 FB15.2 U32.8(VDD)
N30648987: Q11.1(BASE) R438.2
N30648989: R438.1 U32.7(VOUT)
N30648999: C521.2 R439.1 R440.2 U32.1(VIN)
N30649056: J1.2 Q11.3(COLLECTOR)

Not connected (* = marked no-connect by the designer): P1 SHLD3* SHLD4*; P4 6(KEY)* 17(EMU2)* 18(EMU3)* 19(EMU4)*; P5 9 19 M1* M2* SHLD3* SHLD4*; U5 B1(SMPS7_FDBK)* B4(GPADC_REF) C9(NC4)* C11(RPWRON) D1(SMPS7_SW_1) D2(SMPS7_SW_2) D3(SMPS7_SW_3)* J8(SMPS9_FBK)* K4(NC2)* K5(NC5)* K10(GPIO_4/SYSEN1)* L4(NC3)* M7(SMPS9_SW)* M11(CLK32KGO)* N7(SMPS9_SW_1)* N11(GPIO_6/SYSEN2)*; U11 AD14(RTC_OSC_XO)*; U13 3(~{MR}); U14 13(NC1)* 47(NC)*; U32 5(NC)* 6(~{OTF})*

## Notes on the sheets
sheet 1
- REV
- DESCRIPTION
- DATE
- BY
- P01 TITLE PAGE
- P02 12V INPUT, 3.3V AND 5V SWITCHERS
- B
- Production Release
- 11/23/2015
- EPD
- P03 TPS6590374 1 CONTROL
- P04 TPS6590374 2 RESET, & RTC
- P05 TPS6590374 3  MPU,DDR, & DSP SWITCHERS
- P06 TPS6590374 4 CORE & 1.8V
- P07 AM5728 CORE POWER & EEPROM
- P08 AM5728 CLOCKS AND RESET
- P09 AM5728 IO POWER AND GROUND
- P10 AM5728 DDR3 POWER & JTAG
- P11 AM5728 ETHERNET 1
- P12 AM5728 ETHERNET 2
- P13 AM5728 GPMC & LCD
- P14 AM5728 USB INTERFACES
- P15 AM5728 I/O, LEDs, AND GPIO
- P16 AM5728 AUDIO & DEBUG SERIAL
- P17 AM5728 HDMI PORT
- P18 AM5728 eMMC, MMC3, & uSD
- P19 AM5728 DDR INTERFACE 1
- P20 AM5728 DDR INTERFACE 2
- P21 DDR3 BANK 1
- P22 DDR3 BANK 2
- P23 DDR3 BANK 2 CAPS & TERM
- P24 DDR3 BANK 1 CAPS & TERM
- P25 USB & SATA CONNECTOR
- P26 PCIe, SATA, & SERDES CLOCK
- P27 EXPANSION HEADERS
- P28 MECHANICAL
- This schematic is  *NOT SUPPORTED* and DOES NOT constitute a reference design. Only
  “community” support is allowed via resources at BeagleBoard.org/discuss.
  THERE IS NO WARRANTY FOR THIS DESIGN , TO THE EXTENT PERMITTED BY APPLICABLE LAW. EXCEPT
  WHEN OTHERWISE STATED IN WRITING THE COPYRIGHT HOLDERS AND/OR OTHER PARTIES PROVIDE THE
  DESIGN “AS IS” WITHOUT WARRANTY OF ANY KIND, EITHER EXPRESSED OR IMPLIED, INCLUDING, BUT
  NOT LIMITED TO, THE IMPLIED WARRANTIES OF MERCHANTABILITY AND FITNESS FOR A PARTICULAR
  PURPOSE. THE ENTIRE RISK AS TO THE QUALITY AND PERFORMANCE OF THE DESIGN IS WITH YOU.
  SHOULD THE DESIGN PROVE DEFECTIVE, YOU ASSUME THE COST OF ALL NECESSARY SERVICING,
  REPAIR OR CORRECTION.
sheet 2
- VBATT
  12V
- 12VDC TO 5VDC 4A
- 4A
- DUAL OPTION JACK
  PJ-063BH & PJ-080BH
- 5V
- AUXILLIARY 5VDC
  FAN CONNECTOR.
- 12VDC MAIN POWER INPUT
- Undervoltage lockout..11.6V
- DC
- 12VDC TO 3.3VDC 4A
- POWER LED
- Undervoltage lockout..11.6V
- TEMPERATURE SENSOR
- Place at ESD ring
  Near 4200, 3300
sheet 3
- Y9 OPTIONAL PACKAGE
  CHANGE C452 & C453
  VALUE AS NEEDED
- PMIC
- BOOT0=0=1.35V DDR
  BOOT1=1=WarmReset PORz Pulse
- POWER BUTTON
- TPS6590376ZWSR
- Insert wire here to enable
  use of the JTAG without
  boot image present.
  Otherwise board will
  power off.
sheet 4
- 3.3V (3.3V I/O)
- Single point power connection.
- 1.8V
- 3.3V
- 3.3V
- 1.8V
- 1.0V
- 1.8V
- TPS6590376ZWSR
- Real Time Clock
- Voltage clamp circuit.
- Voltage clamp circuit.
sheet 6
- Clamp Circuit
sheet 7
- BOARD ID EEPROM
- WRITE ENABLE
sheet 8
- WARM RESET TO
  POWER ON RESET
  TRIGGER.
- 0.9V TRIP
- RESET BUTTON
- SET FOR PORZ ONLY
sheet 10
- JTAG HEADER.
sheet 11
- ETHERNET PORT 0
- PHYAD 0X01
